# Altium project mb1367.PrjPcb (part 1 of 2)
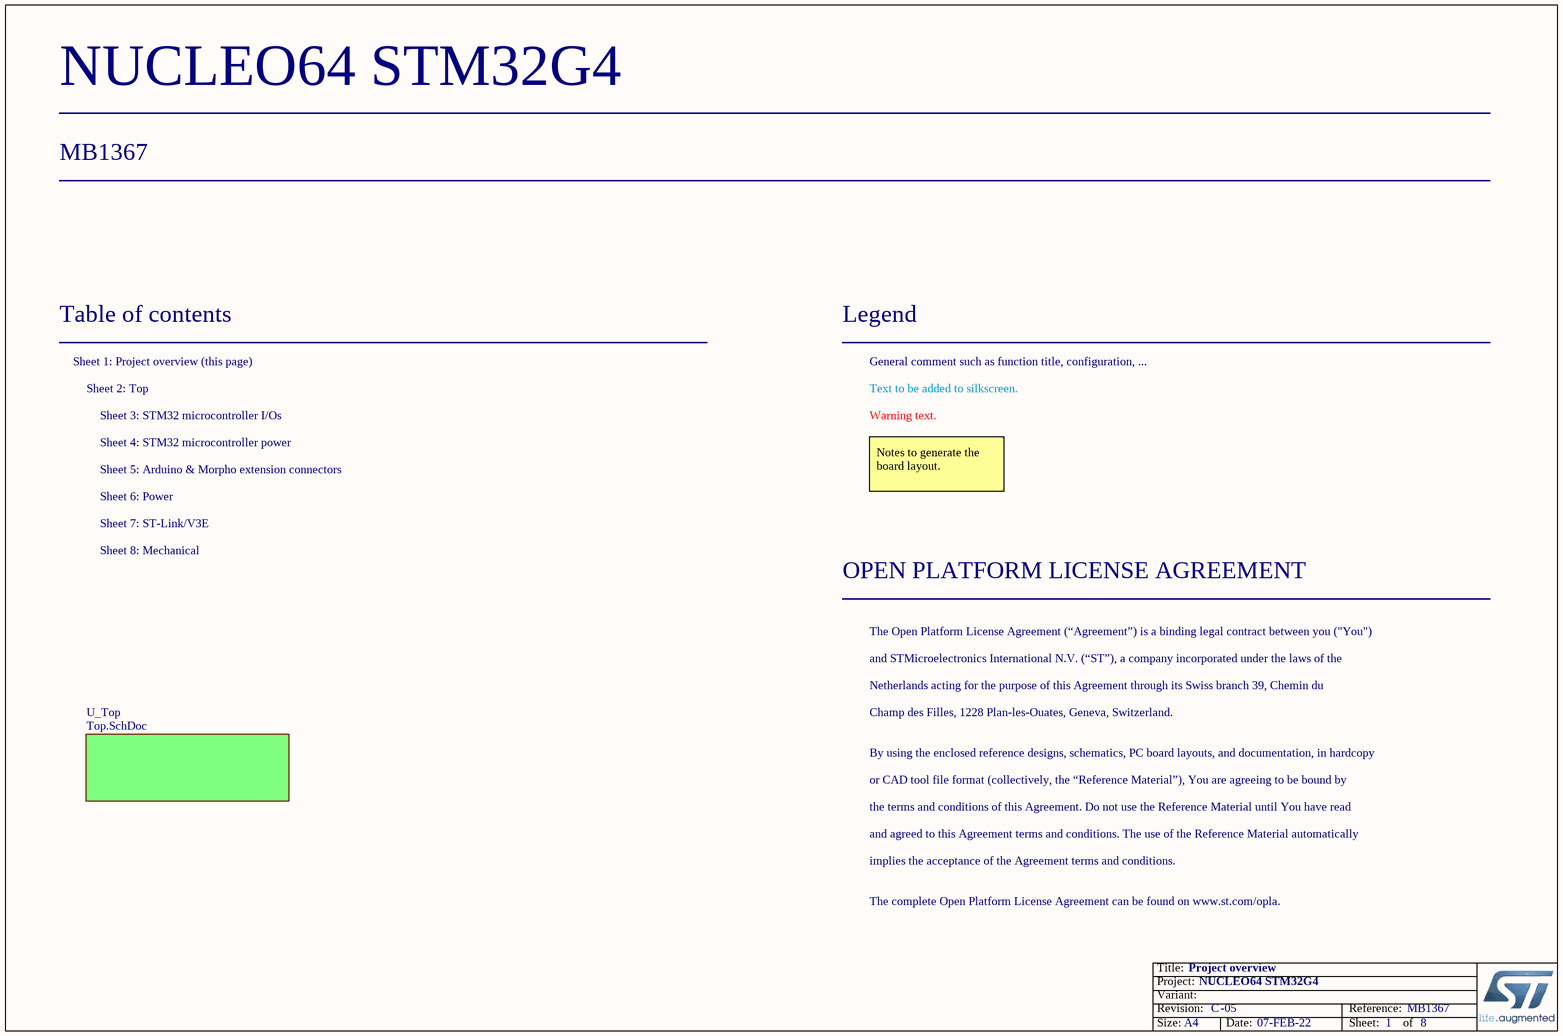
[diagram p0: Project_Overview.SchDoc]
Board_Assembly_Revision: 05; Board_Document_Date: 07-FEB-22; Board_Name: NUCLEO64 STM32G4; Board_PCB_Revision: C; Board_Reference: MB1367
8 sheets, 202 parts. Net scope: flat (ports and power ports of the same name join across sheets).
Board file: MB1367.PcbDoc
Sheets:
  Project_Overview.SchDoc
    U_Top = Top.SchDoc
      U_Arduino_extension_connectors = Arduino_extension_connectors.SchDoc
      U_Power = Power.SchDoc
      U_STM32_microcontroller_IOs = STM32_microcontroller_IOs.SchDoc
      U_STM32_microcontroller_power = STM32_microcontroller_power.SchDoc
      U_ST_LINK_V3E = ST_LINK_V3E.SchDoc
      Mechanical = Mechanical.SchDoc

## Sheet Project_Overview.SchDoc: Project overview
size A4; Date: Not used; ApprovedBy: Not used; CheckedBy: Not used; Author: Not used; CompanyName: STMicroelectronics; DrawnBy: Not used; Engineer: Not used; Organization: Not used; Address1: Not used; Address2: Not used; Address3: Not used; Address4: Not used; DocumentNumber: 1; Revision: Not used; SheetNumber: 1; SheetTotal: 8

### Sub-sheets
U_Top = Top.SchDoc: no entries

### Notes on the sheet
- Table of contents
- Sheet 1: Project overview (this page)
- Legend
- General comment such as function title, configuration, ...
- Sheet 2: Top
- Sheet 4: STM32 microcontroller power
- Sheet 3: STM32 microcontroller I/Os
- Text to be added to silkscreen.
- Warning text.
- Sheet 6: Power
- Sheet 5: Arduino & Morpho extension connectors
- Notes to generate the board layout.
- Sheet 7: ST-Link/V3E
- Sheet 8: Mechanical
- OPEN PLATFORM LICENSE AGREEMENT
- The Open Platform License Agreement (“Agreement”) is a binding legal contract between you ("You")
- and STMicroelectronics International N.V. (“ST”), a company incorporated under the laws of the
- Netherlands acting for the purpose of this Agreement through its Swiss branch 39, Chemin du
- Champ des Filles, 1228 Plan-les-Ouates, Geneva, Switzerland.
- By using the enclosed reference designs, schematics, PC board layouts, and documentation, in hardcopy
- or CAD tool file format (collectively, the “Reference Material”), You are agreeing to be bound by
- the terms and conditions of this Agreement. Do not use the Reference Material until You have read
- and agreed to this Agreement terms and conditions. The use of the Reference Material automatically
- implies the acceptance of the Agreement terms and conditions.
- The complete Open Platform License Agreement can be found on www.st.com/opla.

## Sheet Top.SchDoc: Top hierarchical view
size A4; Date: Not used; ApprovedBy: Not used; CheckedBy: Not used; Author: Not used; CompanyName: STMicroelectronics; DrawnBy: Not used; Engineer: Not used; Organization: Not used; Address1: Not used; Address2: Not used; Address3: Not used; Address4: Not used; DocumentNumber: 2; Revision: A-01-P3; SheetNumber: 2; SheetTotal: 8
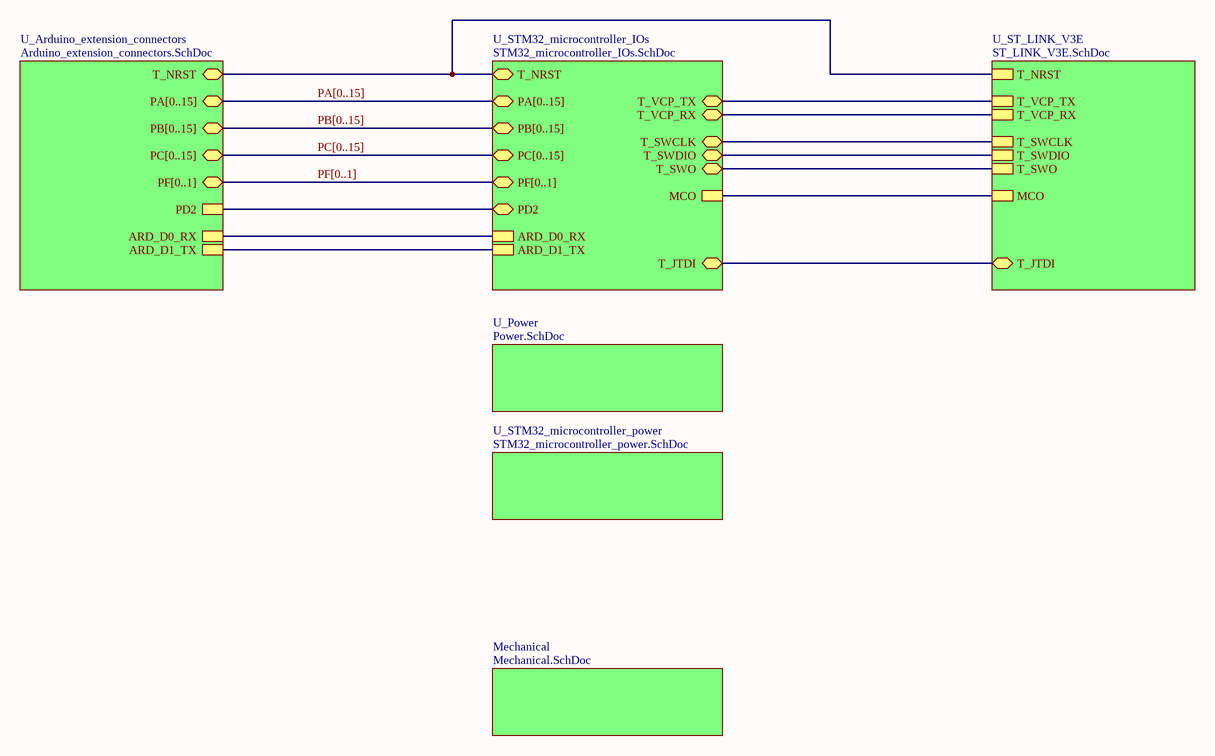
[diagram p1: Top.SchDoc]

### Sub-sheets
Mechanical = Mechanical.SchDoc: no entries
U_Arduino_extension_connectors = Arduino_extension_connectors.SchDoc: PA[0..15] (bidir), PB[0..15] (bidir), PC[0..15] (bidir), PD2, PF[0..1] (bidir), ARD_D0_RX, ARD_D1_TX, T_NRST
U_Power = Power.SchDoc: no entries
U_ST_LINK_V3E = ST_LINK_V3E.SchDoc: T_SWCLK, T_SWO, T_NRST, MCO, T_SWDIO, T_VCP_TX, T_VCP_RX, T_JTDI
U_STM32_microcontroller_IOs = STM32_microcontroller_IOs.SchDoc: PA[0..15] (bidir), PB[0..15] (bidir), PC[0..15] (bidir), PF[0..1] (bidir), ARD_D0_RX, ARD_D1_TX, MCO, PD2, T_NRST, T_VCP_TX, T_VCP_RX, T_SWCLK, T_SWO, T_SWDIO, T_JTDI
U_STM32_microcontroller_power = STM32_microcontroller_power.SchDoc: no entries

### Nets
(unnamed): sheet U_Arduino_extension_connectors/PD2, sheet U_STM32_microcontroller_IOs/PD2
(unnamed): sheet U_Arduino_extension_connectors/ARD_D0_RX, sheet U_STM32_microcontroller_IOs/ARD_D0_RX  [a separate net that carries the same name]
(unnamed): sheet U_Arduino_extension_connectors/ARD_D1_TX, sheet U_STM32_microcontroller_IOs/ARD_D1_TX  [a separate net that carries the same name]
(unnamed): sheet U_Arduino_extension_connectors/T_NRST, sheet U_STM32_microcontroller_IOs/T_NRST, sheet U_ST_LINK_V3E/T_NRST  [a separate net that carries the same name]
(unnamed): sheet U_STM32_microcontroller_IOs/MCO, sheet U_ST_LINK_V3E/MCO  [a separate net that carries the same name]
(unnamed): sheet U_STM32_microcontroller_IOs/T_VCP_TX, sheet U_ST_LINK_V3E/T_VCP_TX  [a separate net that carries the same name]
(unnamed): sheet U_STM32_microcontroller_IOs/T_VCP_RX, sheet U_ST_LINK_V3E/T_VCP_RX  [a separate net that carries the same name]
(unnamed): sheet U_STM32_microcontroller_IOs/T_SWCLK, sheet U_ST_LINK_V3E/T_SWCLK  [a separate net that carries the same name]
(unnamed): sheet U_STM32_microcontroller_IOs/T_SWO, sheet U_ST_LINK_V3E/T_SWO  [a separate net that carries the same name]
(unnamed): sheet U_STM32_microcontroller_IOs/T_SWDIO, sheet U_ST_LINK_V3E/T_SWDIO  [a separate net that carries the same name]
(unnamed): sheet U_STM32_microcontroller_IOs/T_JTDI, sheet U_ST_LINK_V3E/T_JTDI  [a separate net that carries the same name]

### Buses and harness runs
bus PA[0..15] = sheet U_Arduino_extension_connectors/PA[0..15] = sheet U_STM32_microcontroller_IOs/PA[0..15]
bus PB[0..15] = sheet U_Arduino_extension_connectors/PB[0..15] = sheet U_STM32_microcontroller_IOs/PB[0..15]
bus PC[0..15] = sheet U_Arduino_extension_connectors/PC[0..15] = sheet U_STM32_microcontroller_IOs/PC[0..15]
bus PF[0..1] = sheet U_Arduino_extension_connectors/PF[0..1] = sheet U_STM32_microcontroller_IOs/PF[0..1]

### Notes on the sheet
- Cuttable part on PCB

## Sheet Arduino_extension_connectors.SchDoc: Arduino & Morpho extension connectors
size A4; Date: Not used; ApprovedBy: Not used; CheckedBy: Not used; Author: Not used; CompanyName: STMicroelectronics; DrawnBy: Not used; Engineer: Not used; Organization: Not used; Address1: Not used; Address2: Not used; Address3: Not used; Address4: Not used; DocumentNumber: 5; Revision: Not used; SheetNumber: 5; SheetTotal: 8
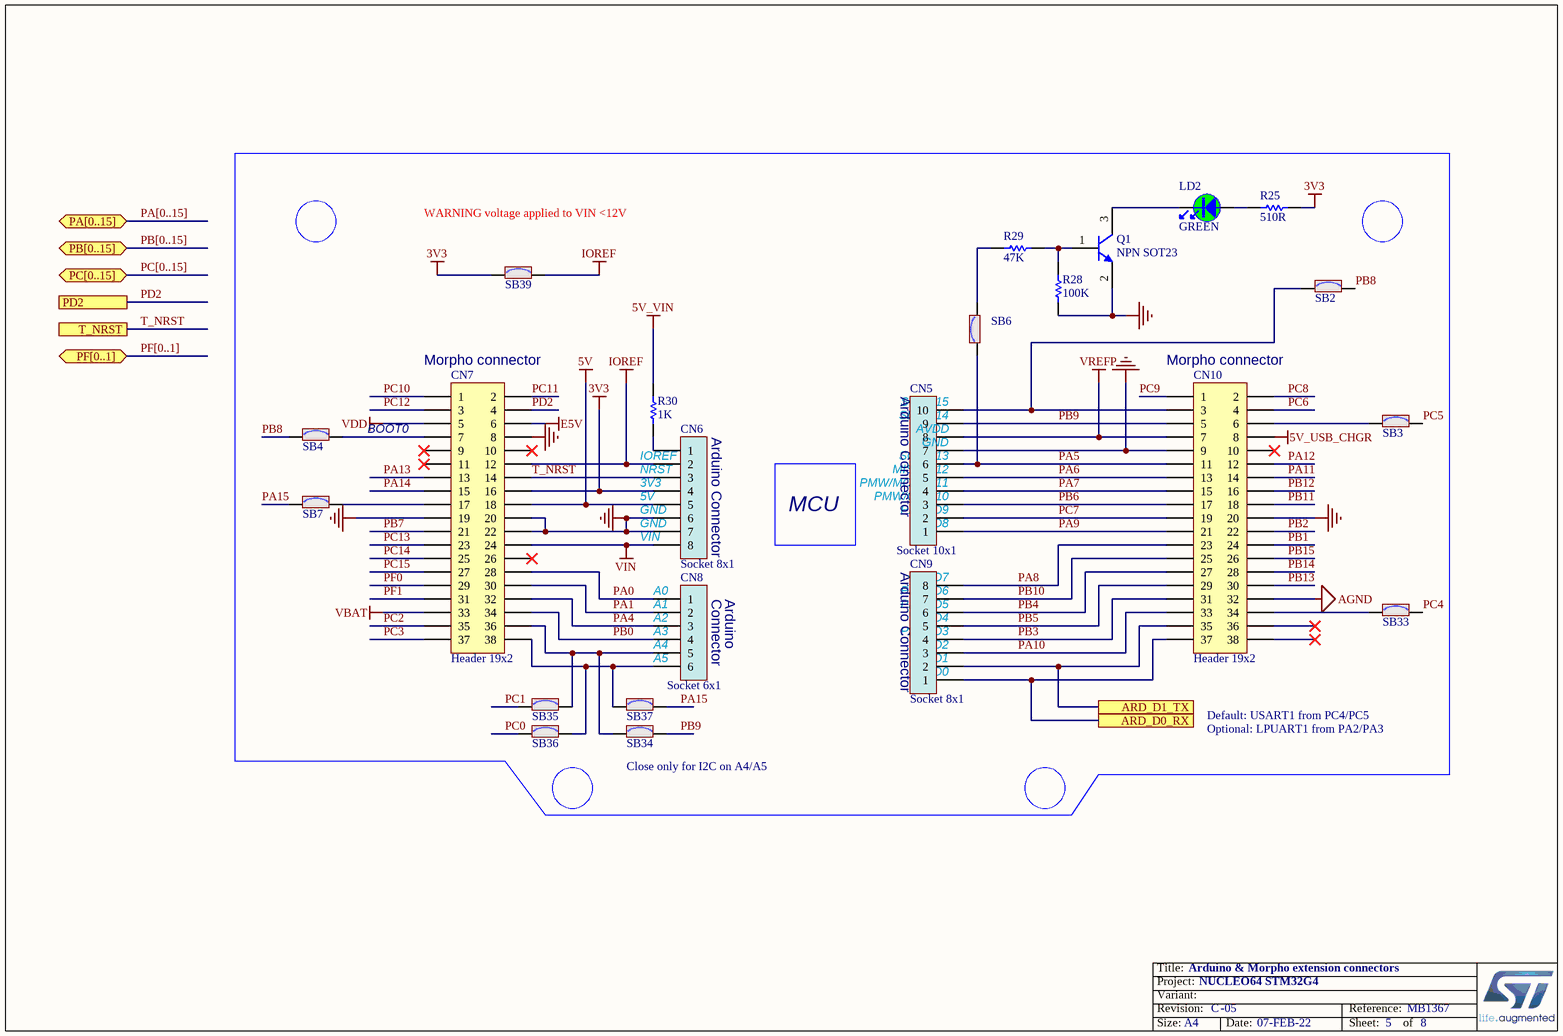
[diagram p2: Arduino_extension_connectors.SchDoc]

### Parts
CN5  value Socket 10x1  [CON_SAMTEC_SSW-110-03-X-S]
CN6  value Socket 8x1  [CON_SAMTEC_SSW-108-03-X-S]
CN7  value Header 19x2  [CON_SAMTEC_TSW-119-09-X-D]
CN8  value Socket 6x1  [CON_SAMTEC_SSW-106-03-X-S]
CN9  value Socket 8x1  [CON_SAMTEC_SSW-108-03-X-S]
CN10  value Header 19x2  [CON_SAMTEC_TSW-119-09-X-D]
LD2  value GREEN  [LED_0603_GREEN]  (hidden comment: LED_green)
Q1  value NPN SOT23  [NPN_SOT23]
R25  value 510R  [R0603]
R28  value 100K  [R0603]
R29  value 47K  [R0603]
R30  value 1K  [R0603]
SB2  (no value)  [SOLDER-BRIDGE_R0603-0R]
SB3  (no value)  [SOLDER-BRIDGE_R0603-0R]
SB4  (no value)  [SOLDER-BRIDGE_R0603-0R]
SB6  (no value)  [SOLDER-BRIDGE_R0603-0R]
SB7  (no value)  [SOLDER-BRIDGE_R0603-0R]
SB33  (no value)  [SOLDER-BRIDGE_R0603-0R]
SB34  (no value)  [SOLDER-BRIDGE_R0603-0R]
SB35  (no value)  [SOLDER-BRIDGE_R0603-0R]
SB36  (no value)  [SOLDER-BRIDGE_R0603-0R]
SB37  (no value)  [SOLDER-BRIDGE_R0603-0R]
SB39  (no value)  [SOLDER-BRIDGE_R0603-0R]

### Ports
ARD_D0_RX, ARD_D1_TX, PA[0..15] (bidir), PB[0..15] (bidir), PC[0..15] (bidir), PD2, PF[0..1] (bidir), T_NRST

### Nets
3V3: CN6.4 CN7.16 R25.1 SB39.1
5V: CN6.5 CN7.18
5V_USB_CHGR: CN10.8
5V_VIN: R30.2
AGND: CN10.32
E5V: CN7.6
GND: CN5.7 CN6.6 CN6.7 CN7.8 CN7.19 CN7.20 CN7.22 CN10.9 CN10.20 Q1.2(E) R28.1
IOREF: CN6.2 CN7.12 SB39.2
VBAT: CN7.33
VDD: CN7.5
VIN: CN6.8 CN7.24
VREFP: CN5.8 CN10.7
ARD_D0_RX: CN9.1 CN10.37 ; port ARD_D0_RX
ARD_D1_TX: CN9.2 CN10.35 ; port ARD_D1_TX
PA0: CN7.28 CN8.1
PA1: CN7.30 CN8.2
PA4: CN7.32 CN8.3
PA5: CN5.6 CN10.11 SB6.1
PA6: CN5.5 CN10.13
PA7: CN5.4 CN10.15
PA8: CN9.8 CN10.23
PA9: CN5.1 CN10.21
PA10: CN9.3 CN10.33
PA11: CN10.14
PA12: CN10.12
PA13: CN7.13
PA14: CN7.15
PA15: SB7.1 SB37.2
PB0: CN7.34 CN8.4
PB1: CN10.24
PB2: CN10.22
PB3: CN9.4 CN10.31
PB4: CN9.6 CN10.27
PB5: CN9.5 CN10.29
PB6: CN5.3 CN10.17
PB7: CN7.21
PB8: SB2.2 SB4.1
PB9: CN5.9 CN10.5 SB34.2
PB10: CN9.7 CN10.25
PB11: CN10.18
PB12: CN10.16
PB13: CN10.30
PB14: CN10.28
PB15: CN10.26
PC0: SB36.1
PC1: SB35.1
PC2: CN7.35
PC3: CN7.37
PC4: SB33.2
PC5: SB3.2
PC6: CN10.4
PC7: CN5.2 CN10.19
PC8: CN10.2
PC9: CN10.1
PC10: CN7.1
PC11: CN7.2
PC12: CN7.3
PC13: CN7.23
PC14: CN7.25
PC15: CN7.27
PD2: CN7.4 ; port PD2
PF0: CN7.29
PF1: CN7.31
T_NRST: CN6.3 CN7.14 ; port T_NRST
NetCN5_10: CN5.10 CN10.3 SB2.1
NetCN6_1: CN6.1 R30.1
NetCN7_7: CN7.7 SB4.2
NetCN7_17: CN7.17 SB7.2
NetCN7_36: CN7.36 CN8.5 SB34.1 SB35.2
NetCN7_38: CN7.38 CN8.6 SB36.2 SB37.1
NetCN10_6: CN10.6 SB3.1
NetCN10_34: CN10.34 SB33.1
NetLD2_1: LD2.1 R25.2
NetLD2_2: LD2.2 Q1.3(C)
NetQ1_1: Q1.1(B) R28.2 R29.2
NetR29_1: R29.1 SB6.2

Not connected (* = marked no-connect by the designer): CN7 9* 10* 11* 26*; CN10 10* 36* 38*

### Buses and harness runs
bus PA[0..15] = port PA[0..15]
bus PB[0..15] = port PB[0..15]
bus PC[0..15] = port PC[0..15]
bus PF[0..1] = port PF[0..1]

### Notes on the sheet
- WARNING voltage applied to VIN <12V
- (near CN7) Morpho connector
- (near CN10) Morpho connector
- (near CN7) BOOT0
- (near CN6) Arduino Connector
- (near CN5) Arduino Connector
- (near CN5) SDA/D14
- (near CN5) SCL/D15
- (near CN5) AVDD
- (near CN5) GND
- (near CN6) GND
- (near CN6) 5V
- (near CN6) 3V3
- (near CN6) NRST
- (near CN6) IOREF
- MCU
- (near CN5) PMW/D9
- (near CN5) PMW/CS/D10
- (near CN5) SCK/D13
- (near CN5) MISO/D12
- (near CN5) PMW/MOSI/D11
- (near CN6) VIN
- (near CN9) Arduino Connector
- (near CN9) D7
- (near CN5) D8
- (near CN8) A0
- (near CN8) A1
- (near CN8) A2
- (near CN8) A3
- (near CN8) A4
- (near CN8) Connector
- (near CN8) Arduino
- (near CN9) D2
- (near CN9) D4
- (near CN9) PMW/D3
- (near CN9) PMW/D5
- (near CN9) PMW/D6
- (near CN8) A5
- (near CN9) RX/D0
- (near CN9) TX/D1
- (near SB34) Close only for I2C on A4/A5
- Default: USART1 from PC4/PC5
  Optional: LPUART1 from PA2/PA3

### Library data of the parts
CN5 = MCD-00262: Socket, 10x1, 2.54mm, VR, TH, Height 8.51mm/10mm; Manufacturer_Part_Number: SSW-110-03-x-S; Manufacturer: SAMTEC; Part_Type: Connector; Provided_By: SUBCO
CN6 CN9 = MCD-00261: Socket, 8x1, 2.54mm, VR, TH, Height 8.51mm/10mm; Manufacturer_Part_Number: SSW-108-03-x-S; Manufacturer: SAMTEC; Part_Type: Connector; Provided_By: SUBCO
CN7 CN10 = MCD-00213: Header, 19x2, 2,54mm, VR, TH, Height 5.84mm/10.16mm; Manufacturer_Part_Number: TSW-119-09-x-D; Manufacturer: SAMTEC; Part_Type: Connector; Provided_By: SUBCO
CN8 = MCD-00260: Socket, 6x1, 2.54mm, VR, TH, Height 8.51mm/10mm; Manufacturer_Part_Number: SSW-106-03-x-S; Manufacturer: SAMTEC; Part_Type: Connector; Provided_By: SUBCO
LD2 = MCD-02520: LED, GREEN, 0603, VF : 2.4V max ; IF: 20mA; Part_Type: Display; Part_Preference: Recommended; Manufacturer: OSRAM OPTO SEMICONDUCTORS; Manufacturer_Part_Number: LG Q396-PS-35; ShowFields: YES; ID: 4626
Q1 = MCD-00073: NPN Bipolar Transistor; Part_Type: IC; Manufacturer_Part_Number: BSR14; Manufacturer: ON SEMICONDUCTOR; Alternate_Manufacturer_Part_Number: MMBT2222LT1G / MMBT2222ALT1G / MMBT2222ALT3G; ECCN_US: EAR99; ECCN_EU: NEC; Provided_By: SUBCO
R25 = MCD-00225: Resistor,510R,0603,1%,1/10W; Manufacturer_Part_Number: RC0603FR-07510RL; Manufacturer: YAGEO; ECCN_US: EAR99; ECCN_EU: NEC; Provided_By: SUBCO
R28 = MCD-00223: Resistor,100K,0603,1%,1/10W; Manufacturer_Part_Number: RC0603FR-07100KL; Manufacturer: YAGEO; Provided_By: Subcon; Initial_Board_Reference: MB1319
R29 = MCD-00222: Resistor,47K,0603,1%,1/10W; Manufacturer_Part_Number: RC0603FR-0747KL; Manufacturer: YAGEO; ECCN_US: EAR99; ECCN_EU: NEC; Provided_By: SUBCO
R30 = MCD-00070: Resistor,1K,0603,1%,1/10W; Manufacturer_Part_Number: RC0603FR-071KL; Manufacturer: YAGEO; Provided_By: Subcon; Initial_Board_Reference: MB1274
SB2-SB4 SB6 SB7 SB33-SB37 SB39 = MCD-00071: Solder Bridge ON; Part_Type: Mechanical; Manufacturer_Part_Number: RC0603JR-070RL; Manufacturer: YAGEO; Provided_By: SUBCO

## Sheet Power.SchDoc: Main power 5V / 3V3
size A4; Date: Not used; ApprovedBy: Not used; CheckedBy: Not used; Author: Not used; CompanyName: STMicroelectronics; DrawnBy: Not used; Engineer: Not used; Organization: Not used; Address1: Not used; Address2: Not used; Address3: Not used; Address4: Not used; DocumentNumber: 6; Revision: Not used; SheetNumber: 6; SheetTotal: 8
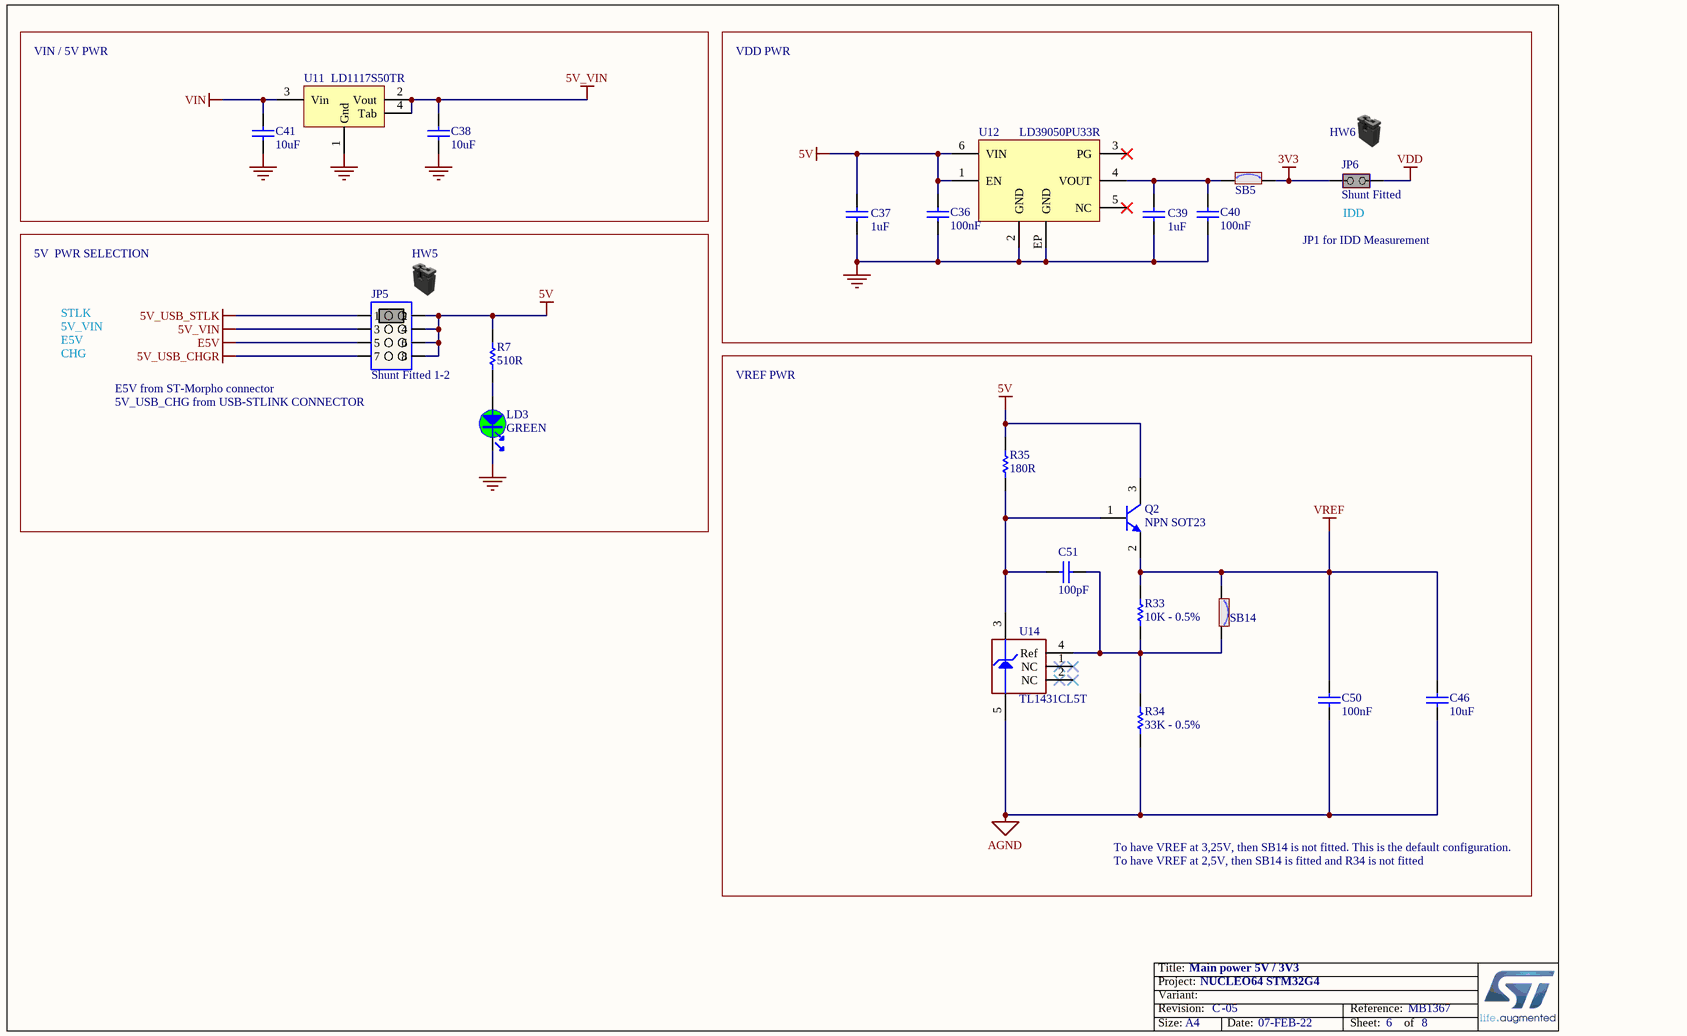
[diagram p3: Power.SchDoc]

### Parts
C36  value 100nF  [C0402]
C37  value 1uF  [C0603]
C38  value 10uF  [C0805]
C39  value 1uF  [C0603]
C40  value 100nF  [C0402]
C41  value 10uF  [C0805]
C46  value 10uF  [C0603]
C50  value 100nF  [C0603]
C51  value 100pF  [C0603]
HW5  (no value)  (mechanical)
HW6  (no value)  (mechanical)
JP5  value Shunt Fitted 1-2  [CON_SAMTEC_TSW-104-07-X-D]
JP6  Shunt Fitted  [CON_SAMTEC_TSW-102-07-G-S]
LD3  value GREEN  [LED_0603_GREEN]  (hidden comment: LED_green)
Q2  value NPN SOT23  [NPN_SOT23]
R7  value 510R  [R0603]
R33  value 10K - 0.5%  [R0603]
R34  value 33K - 0.5%  [R0603]
R35  value 180R  [R0603]
SB5  (no value)  [SOLDER-BRIDGE_R0603-0R]
SB14  (no value)  [SOLDER-BRIDGE_R0603-0R]
U11  value LD1117S50TR  [REG_SOT223-TAB]
U12  value LD39050PU33R  [ICC_DFN6-EPAD_3X3_P095]
U14  value TL1431CL5T  [ICC_SOT23-5L_H1P45]

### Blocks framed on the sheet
VIN / 5V PWR: C38 C41 U11
VREF PWR: C46 C50 C51 Q2 R33-R35 SB14 U14

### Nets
3V3: JP6.1(COMMON) SB5.2
5V: C36.2 C37.2 JP5.2 JP5.4 JP5.6 JP5.8 Q2.3(C) R7.2 R35.2 U12.1(EN) U12.6(VIN)
5V_USB_CHGR: JP5.7
5V_USB_STLK: JP5.1
5V_VIN: C38.2 JP5.3 U11.2(Vout) U11.4(Tab)
AGND: C46.1 C50.1 R34.1 U14.5(Anode)
E5V: JP5.5
GND: C36.1 C37.1 C38.1 C39.1 C40.1 C41.1 LD3.2 U11.1(Gnd) U12.2(GND) U12.EP(GND)
VDD: JP6.2(NO)
VIN: C41.2 U11.3(Vin)
VREF: C46.2 C50.2 Q2.2(E) R33.2 SB14.1
NetC39_2: C39.2 C40.2 SB5.1 U12.4(VOUT)
NetC51_1: C51.1 Q2.1(B) R35.1 U14.3(Cathode)
NetC51_2: C51.2 R33.1 R34.2 SB14.2 U14.4(Ref)
NetLD3_1: LD3.1 R7.1

Not connected (* = marked no-connect by the designer): U12 3(PG)* 5(NC)*; U14 1(NC)* 2(NC)*

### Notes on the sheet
- VDD PWR
- JP1 for IDD Measurement
- (near JP6) IDD
- 5V  PWR SELECTION
- STLK
- E5V
- 5V_VIN
- CHG
- E5V from ST-Morpho connector
- 5V_USB_CHG from USB-STLINK CONNECTOR
- To have VREF at 3,25V, then SB14 is not fitted. This is the default configuration.
- To have VREF at 2,5V, then SB14 is fitted and R34 is not fitted

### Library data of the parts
C36 C40 = MCD-00102: Capacitor, MLCC, 100nF, 16V, X7R, 10%, 0402, T=0,5mm; Manufacturer_Part_Number: CC0402KRX7R7BB104; Manufacturer: YAGEO; Provided_By: Subcon; Initial_Board_Reference: MB1262
C37 C39 = MCD-00010: Capacitor, MLCC, 1uF, 16V, X5R, 10%, 0603, T=0,8mm; Manufacturer_Part_Number: CC0603KRX5R7BB105; Manufacturer: YAGEO; Provided_By: Subcon; Initial_Board_Reference: MB1274
C38 C41 = MCD-00014: Capacitor, MLCC, 10uF, 25V, X5R, 10%, 0805, T=0,85mm; Manufacturer_Part_Number: CC0805KRX5R8BB106; Manufacturer: YAGEO; ECCN_US: EAR99; ECCN_EU: NEC; Provided_By: SUBCO
C46 = MCD-01124: Capacitor, MLCC, 10uF, 10V, X5R, 10%, 0603, T=0.8mm; Manufacturer_Part_Number: GRM188R61A106KAAL; Manufacturer: MURATA; ECCN_US: EAR99; ECCN_EU: NEC; Provided_By: SUBCO
C50 = MCD-00211: Capacitor, MLCC, 100nF, 16V, X7R, 10%, 0603, T=0,8mm; Manufacturer_Part_Number: CC0603KRX7R7BB104; Manufacturer: YAGEO; ECCN_US: EAR99; ECCN_EU: NEC; Provided_By: SUBCO
C51 = MCD-01101: Capacitor,100pF,50V,X7R,10%,0603; Manufacturer_Part_Number: 06035C101JAT4A; Manufacturer: AVX; ECCN_US: EAR99; ECCN_EU: NEC; Provided_By: SUBCO
HW5 HW6 = MCD-00043: SHUNT 2.54mm BLACK; Manufacturer_Part_Number: SNT-100-BK-G; Manufacturer: SAMTEC; Part_Type: Mechanical; Provided_By: Subcon; Initial_Board_Reference: MB1274
JP5 = MCD-00686: Header, 4x2, 2,54mm, VR, TH, Height 5.84mm/2.54mm - Shunt Fitted 1-2; Part_Type: Connector; Manufacturer_Part_Number: TSW-104-07-x-D; Manufacturer: SAMTEC; Provided_By: SUBCO
JP6 = MCD-00683: Header, 2x1, 2,54mm, VR, TH, Height 5.84mm/2.54mm - Shunt Fitted by default; Part_Type: Connector; Manufacturer_Part_Number: TSW-102-07-x-S; Manufacturer: SAMTEC; Provided_By: Subcon; Initial_Board_Reference: MB1331
LD3 = MCD-02520: as LD2 on sheet Arduino_extension_connectors
Q2 = MCD-00073: as Q1 on sheet Arduino_extension_connectors
R7 = MCD-00225: as R25 on sheet Arduino_extension_connectors
R33 = MCD-01215: resistor, 10K, 0603, 0.5%, 1/10W; Manufacturer_Part_Number: RC0603DR-0710KL; Manufacturer: YAGEO; ECCN_US: EAR99; ECCN_EU: NEC; Provided_By: SUBCO
R34 = MCD-01209: Resistor,33K,0603,0.5%,1/10W; Manufacturer_Part_Number: RC0603DR-0733KL; Manufacturer: YAGEO; ECCN_US: EAR99; ECCN_EU: NEC; Provided_By: SUBCO
R35 = MCD-00342: Resistor,180R,0603,1%,1/10W; Manufacturer_Part_Number: RC0603FR-07180RL; Manufacturer: YAGEO; ECCN_US: EAR99; ECCN_EU: NEC; Provided_By: SUBCO
SB5 SB14 = MCD-00071: as SB2 on sheet Arduino_extension_connectors
U11 = MCD-00088: IC REG LDO 5V 0.8A SOT223; Manufacturer: STMICROELECTRONICS; BMS_Part_Number: 9176133; ECCN_US: EAR99; ECCN_EU: NEC; Provided_By: SUBCO with ST control
U12 = MCD-00215: Low quiescent current and low noise voltage regulators; Manufacturer: STMICROELECTRONICS; Part_Type: IC; BMS_Part_Number: 9176126; ECCN_US: EAR99; ECCN_EU: NEC; Provided_By: SUBCO with ST control
U14 = MCD-01802: Programmable voltage reference with 0.4% voltage precision; Part_Type: IC; Manufacturer: STMICROELECTRONICS; BMS_Part_Number: 9176334; ECCN_US: EAR99; ECCN_EU: NEC; Provided_By: SUBCO with ST control

## Sheet STM32_microcontroller_IOs.SchDoc: STM32 microcontroller I/Os
size A4; Date: Not used; ApprovedBy: Not used; CheckedBy: Not used; Author: Not used; CompanyName: STMicroelectronics; DrawnBy: Not used; Engineer: Not used; Organization: Not used; Address1: Not used; Address2: Not used; Address3: Not used; Address4: Not used; DocumentNumber: 3; Revision: Not used; SheetNumber: 3; SheetTotal: 8
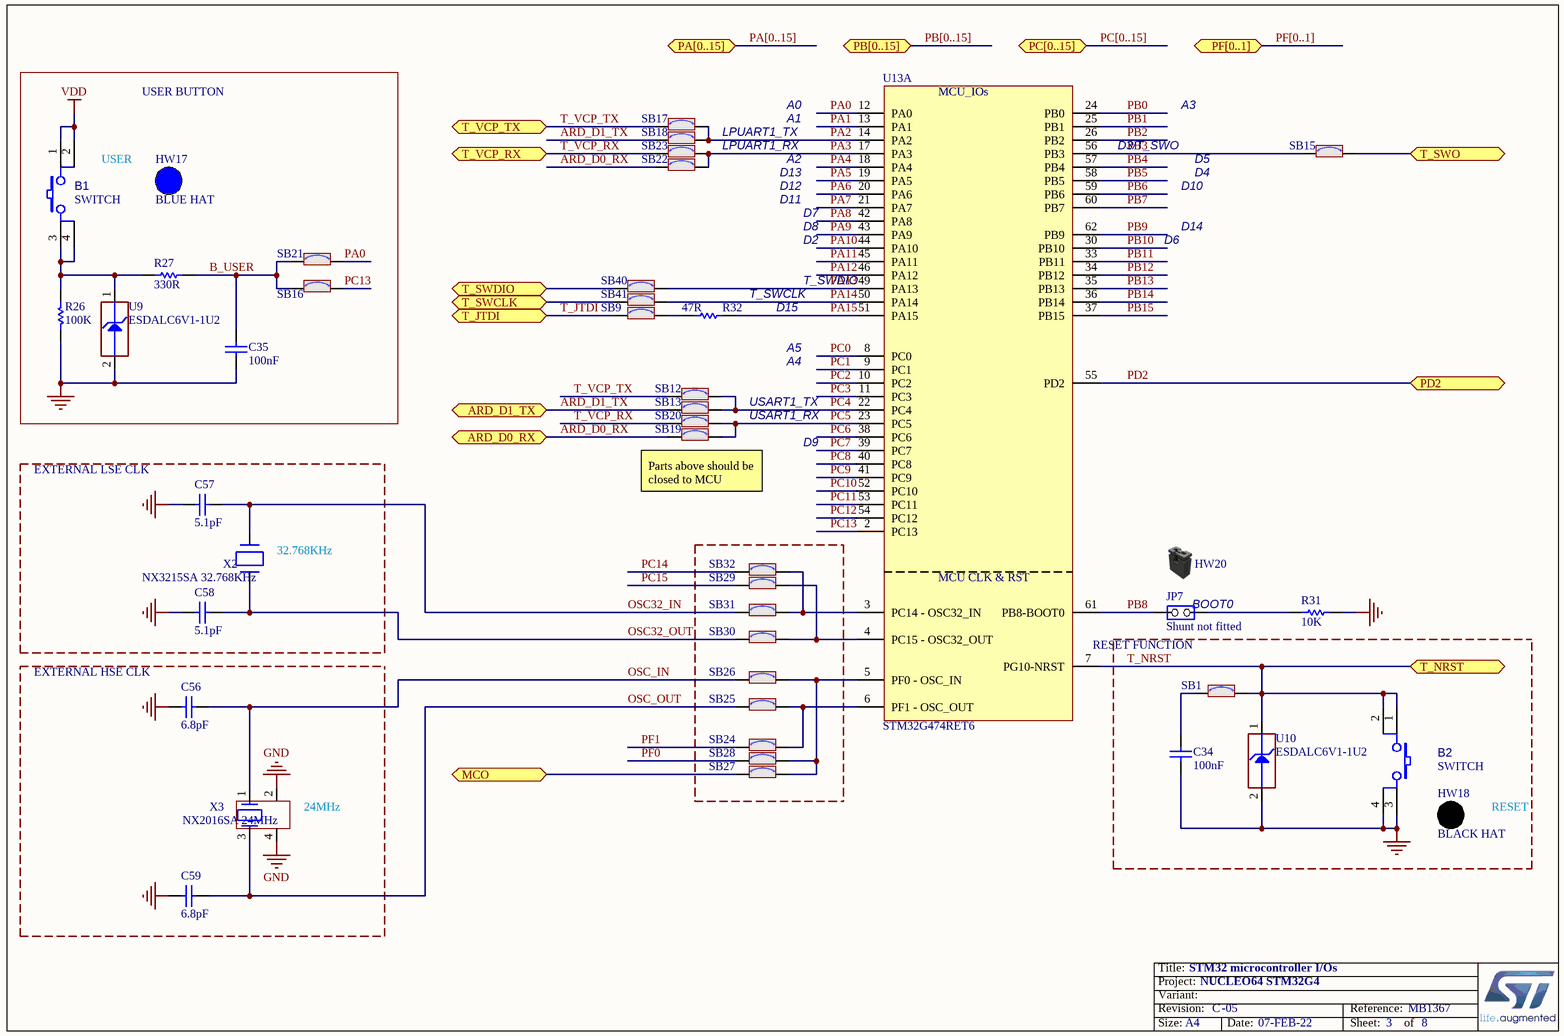
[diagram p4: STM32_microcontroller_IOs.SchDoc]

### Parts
B1  value SWITCH  [SWI_WEALTHMETAL_TD-0341_4P_BLUE]
B2  value SWITCH  [SWI_WEALTHMETAL_TD-0341_4P_BLACK]
C34  value 100nF  [C0402]
C35  value 100nF  [C0402]
C56  value 6.8pF  [C0402]
C57  value 5.1pF  [C0402]
C58  value 5.1pF  [C0402]
C59  value 6.8pF  [C0402]
HW17  value BLUE HAT  (mechanical)
HW18  value BLACK HAT  (mechanical)
HW20  (no value)  (mechanical)
JP7  value Shunt not fitted  [CON_SAMTEC_TSW-102-07-G-S]
R26  value 100K  [R0603]
R27  value 330R  [R0603]
R31  value 10K  [R0603]
R32  value 47R  [R0402]
SB1  (no value)  [SOLDER-BRIDGE_R0603-0R]
SB9  (no value)  [SOLDER-BRIDGE_R0603-0R]
SB12  (no value)  [SOLDER-BRIDGE_R0603-0R]
SB13  (no value)  [SOLDER-BRIDGE_R0603-0R]
SB15  (no value)  [SOLDER-BRIDGE_R0603-0R]
SB16  (no value)  [SOLDER-BRIDGE_R0603-0R]
SB17  (no value)  [SOLDER-BRIDGE_R0603-0R]
SB18  (no value)  [SOLDER-BRIDGE_R0603-0R]
SB19  (no value)  [SOLDER-BRIDGE_R0603-0R]
SB20  (no value)  [SOLDER-BRIDGE_R0603-0R]
SB21  (no value)  [SOLDER-BRIDGE_R0603-0R]
SB22  (no value)  [SOLDER-BRIDGE_R0603-0R]
SB23  (no value)  [SOLDER-BRIDGE_R0603-0R]
SB24  (no value)  [SOLDER-BRIDGE_R0603-0R]
SB25  (no value)  [SOLDER-BRIDGE_R0603-0R]
SB26  (no value)  [SOLDER-BRIDGE_R0603-0R]
SB27  (no value)  [SOLDER-BRIDGE_R0603-0R]
SB28  (no value)  [SOLDER-BRIDGE_R0603-0R]
SB29  (no value)  [SOLDER-BRIDGE_R0603-0R]
SB30  (no value)  [SOLDER-BRIDGE_R0603-0R]
SB31  (no value)  [SOLDER-BRIDGE_R0603-0R]
SB32  (no value)  [SOLDER-BRIDGE_R0603-0R]
SB40  (no value)  [SOLDER-BRIDGE_R0603-0R]
SB41  (no value)  [SOLDER-BRIDGE_R0603-0R]
U9  value ESDALC6V1-1U2  [ESD_ST0201]
U10  value ESDALC6V1-1U2  [ESD_ST0201]
U13  value STM32G474RET6  [ICC_LQFP64_10X10_P050_SOCKET_YAMAICHI_IC149-064-069-B5_NM]  (part A of 2)
X2  value NX3215SA 32.768KHz  [CRY_NX3215SA_2P]
X3  value NX2016SA 24MHz  [CRY_NX2016SA_4P]

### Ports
ARD_D0_RX, ARD_D1_TX, MCO, PA[0..15] (bidir), PB[0..15] (bidir), PC[0..15] (bidir), PD2, PF[0..1] (bidir), T_JTDI, T_NRST, T_SWCLK, T_SWDIO, T_SWO, T_VCP_RX, T_VCP_TX

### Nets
GND: B2.3 B2.4 C34.1 C35.1 C56.1 C57.2 C58.2 C59.1 R26.1 R31.1 U9.2(GND) U10.2(GND) X3.2 X3.4
VDD: B1.1 B1.2
ARD_D0_RX: SB19.2 SB22.2 ; port ARD_D0_RX
ARD_D1_TX: SB13.2 SB18.2 ; port ARD_D1_TX
B_USER: C35.2 R27.2 SB16.1 SB21.1
MCO: SB27.1 ; port MCO
OSC32_IN: C57.1 SB31.1 X2.2(X2)
OSC32_OUT: C58.1 SB30.1 X2.1(X1)
OSC_IN: C56.2 SB26.1 X3.1
OSC_OUT: C59.2 SB25.1 X3.3
PA0: SB21.2 U13.12(PA0)
PA1: U13.13(PA1)
PA2: SB17.2 SB18.1 U13.14(PA2)
PA3: SB22.1 SB23.2 U13.17(PA3)
PA4: U13.18(PA4)
PA5: U13.19(PA5)
PA6: U13.20(PA6)
PA7: U13.21(PA7)
PA8: U13.42(PA8)
PA9: U13.43(PA9)
PA10: U13.44(PA10)
PA11: U13.45(PA11)
PA12: U13.46(PA12)
PA13: SB40.2 U13.49(PA13)
PA14: SB41.2 U13.50(PA14)
PA15: R32.2 U13.51(PA15)
PB0: U13.24(PB0)
PB1: U13.25(PB1)
PB2: U13.26(PB2)
PB3: SB15.1 U13.56(PB3)
PB4: U13.57(PB4)
PB5: U13.58(PB5)
PB6: U13.59(PB6)
PB7: U13.60(PB7)
PB8: JP7.1(COMMON) U13.61(PB8-BOOT0)
PB9: U13.62(PB9)
PB10: U13.30(PB10)
PB11: U13.33(PB11)
PB12: U13.34(PB12)
PB13: U13.35(PB13)
PB14: U13.36(PB14)
PB15: U13.37(PB15)
PC0: U13.8(PC0)
PC1: U13.9(PC1)
PC2: U13.10(PC2)
PC3: U13.11(PC3)
PC4: SB12.2 SB13.1 U13.22(PC4)
PC5: SB19.1 SB20.2 U13.23(PC5)
PC6: U13.38(PC6)
PC7: U13.39(PC7)
PC8: U13.40(PC8)
PC9: U13.41(PC9)
PC10: U13.52(PC10)
PC11: U13.53(PC11)
PC12: U13.54(PC12)
PC13: SB16.2 U13.2(PC13)
PC14: SB32.1
PC15: SB29.1
PD2: U13.55(PD2) ; port PD2
PF0: SB28.1
PF1: SB24.1
T_JTDI: SB9.1 ; port T_JTDI
T_NRST: B2.1 B2.2 SB1.2 U10.1(IO1) U13.7(PG10-NRST) ; port T_NRST
T_SWCLK: SB41.1 ; port T_SWCLK
T_SWDIO: SB40.1 ; port T_SWDIO
T_SWO: SB15.2 ; port T_SWO
T_VCP_RX: SB20.1 SB23.1 ; port T_VCP_RX
T_VCP_TX: SB12.1 SB17.1 ; port T_VCP_TX
NetB1_3: B1.3 B1.4 R26.2 R27.1 U9.1(IO1)
NetC34_2: C34.2 SB1.1
NetJP7_2: JP7.2(NO) R31.2
NetR32_1: R32.1 SB9.2
NetSB24_2: SB24.2 SB25.2 U13.6(PF1_-_OSC_OUT)
NetSB26_2: SB26.2 SB27.2 SB28.2 U13.5(PF0_-_OSC_IN)
NetSB29_2: SB29.2 SB30.2 U13.4(PC15_-_OSC32_OUT)
NetSB31_2: SB31.2 SB32.2 U13.3(PC14_-_OSC32_IN)

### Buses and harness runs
bus PA[0..15] = port PA[0..15]
bus PB[0..15] = port PB[0..15]
bus PC[0..15] = port PC[0..15]
bus PF[0..1] = port PF[0..1]

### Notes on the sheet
- USER BUTTON
- A0
- A3
- USER
- LPUART1_TX
- LPUART1_RX
- A1
- A2
- D13
- D3/T_SWO
- D4
- D5
- D12
- D11
- D2
- D7
- D8
- D14
- D10
- D6
- (near R32) T_SWCLK
- D15
- (near R32) T_SWDIO
- A4
- A5
- USART1_RX
- USART1_TX
- D9
- EXTERNAL LSE CLK
- (near SB19) Parts above should be closed to MCU
- (near X2) 32.768KHz
- RESET FUNCTION
- BOOT0
- EXTERNAL HSE CLK
- (near X3) 24MHz
- RESET

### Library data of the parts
B1 = MCD-00002: Non-Open Push-Button 0.1A 24V; Manufacturer_Part_Number: TD-0341; Manufacturer: WEALTHMETAL; Part_Type: Misc; Provided_By: SUBCO
B2 = MCD-00001: Non-Open Push-Button 0.1A 24V BLACK; Manufacturer_Part_Number: TD-0341; Manufacturer: WEALTHMETAL; Part_Type: Misc; Provided_By: SUBCO
C34 C35 = MCD-00102: as C36 on sheet Power
C56 C59 = MCD-00674: Capacitor, MLCC, 6.8pF, 50V, NPO, +-0.25pF, 0402, T=0.5mm; Manufacturer_Part_Number: CC0402CRNPO9BN6R8; Manufacturer: YAGEO; Provided_By: SUBCO
C57 C58 = MCD-00003: Capacitor, MLCC, 5.1pF, 50V, NPO, +-0.25pF, 0402, T=0.5mm; Manufacturer_Part_Number: CC0402CRNPO9BN5R1; Manufacturer: YAGEO; ECCN_US: EAR99; ECCN_EU: NEC; Provided_By: SUBCO
HW17 = MCD-00634: Blue Hat for switch TD0341X-G01-BLU; Part_Type: Mechanical; Manufacturer_Part_Number: 988.16.09.3.00002_SH-517; Manufacturer: JIUBABA; Provided_By: SUBCO
HW18 = MCD-00635: Black Hat for switch TD0341X-G01-BLA; Part_Type: Mechanical; Manufacturer_Part_Number: 988.16.09.3.00003_SH-517; Manufacturer: JIUBABA; Provided_By: SUBCO
HW20 = MCD-00043: as HW5 on sheet Power
JP7 = MCD-00045: Header, 2x1, 2,54mm, VR, TH, Height 5.84mm/2.54mm; Part_Type: Connector; Manufacturer_Part_Number: TSW-102-07-x-S; Manufacturer: SAMTEC; Provided_By: Subcon; Initial_Board_Reference: MB1274
R26 = MCD-00223: as R28 on sheet Arduino_extension_connectors
R27 = MCD-00197: Resistor,330R,0603,1%,1/10W; Manufacturer_Part_Number: RC0603FR-07330RL; Manufacturer: YAGEO; Provided_By: Subcon
R31 = MCD-00220: Resistor,10K,0603,1%,1/10W; Manufacturer_Part_Number: RC0603FR-0710KL; Manufacturer: YAGEO; Provided_By: Subcon; Initial_Board_Reference: MB1319
R32 = MCD-00481: Resistor,47R,0402,1%,1/16W; Manufacturer_Part_Number: RC0402FR-0747RL; Manufacturer: YAGEO; Provided_By: SUBCO; ECCN_US: EAR99; ECCN_EU: NEC
SB1 SB9 SB12 SB13 SB15-SB32 SB40 SB41 = MCD-00071: as SB2 on sheet Arduino_extension_connectors
U9 U10 = MCD-00170: ESD protection 6V1; Part_Type: Diode; Manufacturer: STMICROELECTRONICS; ECCN_US: EAR99; ECCN_EU: NEC; Provided_By: Subcon; Initial_Board_Reference: MB1274
U13 = MCD-01243: STM32G474, LQFP64 package,  3D IC footprint with 2D socket footprint.; Manufacturer: STMICROELECTRONICS; BMS_Part_Number: 9175326; Provided_By: SUBCO with ST control; ECCN_US: 3A991A2; ECCN_EU: NEC
X2 = MCD-00091: Crystal 32.768kHz, 6pF, +-20ppm, 50Kohms max, SMD; Manufacturer_Part_Number: NX3215SA 32.768KHz EXS00A-MU00525; Manufacturer: NDK; Part_Type: Crystal_Osc; BMS_Part_Number: 9157034; ECCN_US: EAR99; ECCN_EU: NEC; Provided_By: SUBCO
X3 = MCD-01036: Crystal 24MHz, 6pF, +-20ppm, 80ohms max, SMD; Part_Type: Crystal_Osc; Manufacturer_Part_Number: NX2016SA 24MHz EXS00A-CS10820; Manufacturer: NDK; BMS_Part_Number: 9157045; ECCN_US: EAR99; ECCN_EU: NEC; Provided_By: SUBCO

## Sheet STM32_microcontroller_power.SchDoc: STM32 microcontroller power part
size A4; Date: Not used; ApprovedBy: Not used; CheckedBy: Not used; Author: Not used; CompanyName: STMicroelectronics; DrawnBy: Not used; Engineer: Not used; Organization: Not used; Address1: Not used; Address2: Not used; Address3: Not used; Address4: Not used; DocumentNumber: 4; Revision: Not used; SheetNumber: 4; SheetTotal: 8
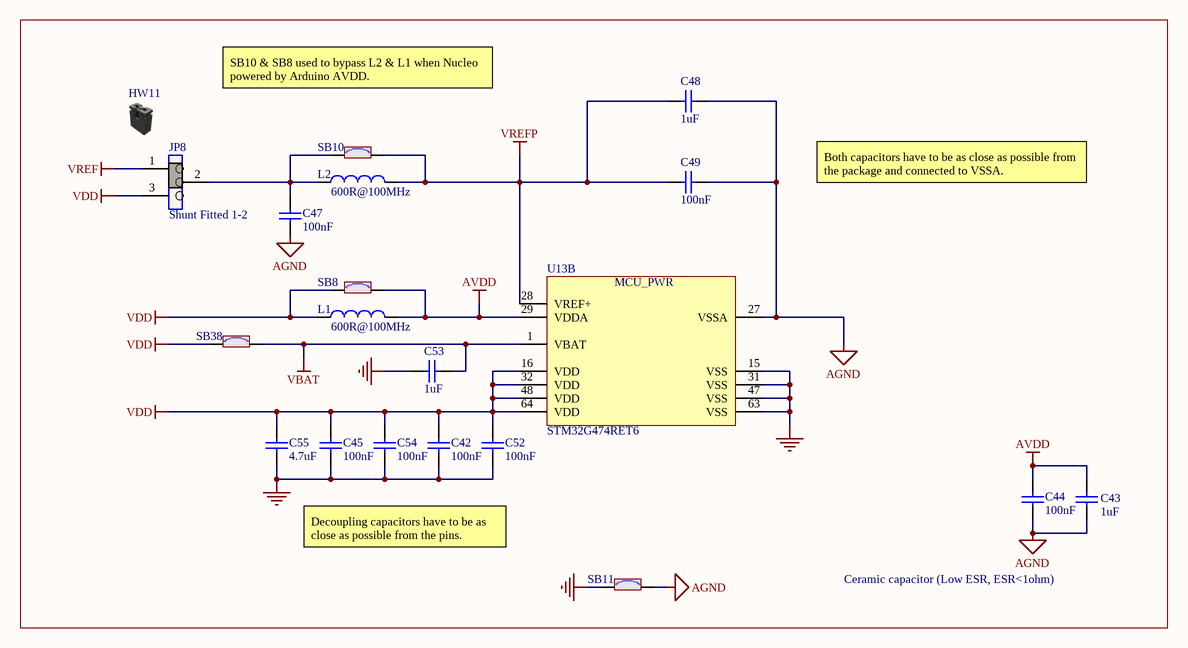
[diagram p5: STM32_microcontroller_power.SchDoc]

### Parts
C42  value 100nF  [C0402]
C43  value 1uF  [C0603]
C44  value 100nF  [C0402]
C45  value 100nF  [C0402]
C47  value 100nF  [C0402]
C48  value 1uF  [C0603]
C49  value 100nF  [C0402]
C52  value 100nF  [C0402]
C53  value 1uF  [C0603]
C54  value 100nF  [C0402]
C55  value 4.7uF  [C0603]
HW11  (no value)  (mechanical)
JP8  value Shunt Fitted 1-2  [CON_SAMTEC_TSW-103-07-F-S]
L1  value 600R@100MHz  [L0603]
L2  value 600R@100MHz  [L0603]
SB8  (no value)  [SOLDER-BRIDGE_R0603-0R]
SB10  (no value)  [SOLDER-BRIDGE_R0603-0R]
SB11  (no value)  [SOLDER-BRIDGE_R0603-0R]
SB38  (no value)  [SOLDER-BRIDGE_R0603-0R]
U13  value STM32G474RET6  [ICC_LQFP64_10X10_P050_SOCKET_YAMAICHI_IC149-064-069-B5_NM]  (part B of 2)

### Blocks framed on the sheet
Ceramic capacitor (Low ESR, ESR<1ohm): C42-C45 C47-C49 C52-C55 HW11 JP8 L1 L2 SB8 SB10 SB11 SB38 U13

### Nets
AGND: C43.1 C44.1 C47.1 C48.2 C49.2 SB11.2 U13.27(VSSA)
AVDD: C43.2 C44.2 L1.2 SB8.2 U13.29(VDDA)
GND: C42.1 C45.1 C52.1 C53.1 C54.1 C55.1 SB11.1 U13.15(VSS) U13.31(VSS) U13.47(VSS) U13.63(VSS)
VBAT: C53.2 SB38.2 U13.1(VBAT)
VDD: C42.2 C45.2 C52.2 C54.2 C55.2 JP8.3 L1.1 SB8.1 SB38.1 U13.16(VDD) U13.32(VDD) U13.48(VDD) U13.64(VDD)
VREF: JP8.1
VREFP: C48.1 C49.1 L2.2 SB10.2 U13.28(VREF+)
NetC47_2: C47.2 JP8.2 L2.1 SB10.1

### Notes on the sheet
- SB10 & SB8 used to bypass L2 & L1 when Nucleo powered by Arduino AVDD.
- Both capacitors have to be as close as possible from the package and connected to VSSA.
- Decoupling capacitors have to be as close as possible from the pins.

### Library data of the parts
C42 C44 C45 C47 C49 C52 C54 = MCD-00102: as C36 on sheet Power
C43 C48 C53 = MCD-00010: as C37 on sheet Power
C55 = MCD-00009: Capacitor, MLCC, 4.7uF, 16V, X5R, 10%, 0603, T=0.8mm; Manufacturer_Part_Number: CC0603KRX5R7BB475; Manufacturer: YAGEO; Provided_By: subcon; Initial_Board_Reference: MB1274
HW11 = MCD-00043: as HW5 on sheet Power
JP8 = MCD-00684: Header, 3x1, 2,54mm, VR, TH, Height 5.84mm/2.54mm - Shunt Fitted 1-2 by default; Part_Type: Connector; Manufacturer_Part_Number: TSW-103-07-F-S; Manufacturer: SAMTEC; Provided_By: SUBCO
L1 L2 = MCD-00047: SMD Chip ferrite bead, 600R@100MHz +/-25%, 350mA, 500mohm DC, 0603, T=0.8mm; Part_Type: Inductor; Manufacturer_Part_Number: FCM1608KF-601T03; Manufacturer: TAI-TECH; Provided_By: SUBCO
SB8 SB10 SB11 SB38 = MCD-00071: as SB2 on sheet Arduino_extension_connectors
U13 = MCD-01243: as U13 on sheet STM32_microcontroller_IOs

## Sheet ST_LINK_V3E.SchDoc: STLINK_V3E
size A3; Date: Not used; ApprovedBy: Not used; CheckedBy: Not used; Author: Not used; CompanyName: STMicroelectronics; DrawnBy: Not used; Engineer: Not used; Organization: Not used; Address1: Not used; Address2: Not used; Address3: Not used; Address4: Not used; DocumentNumber: 7; Revision: Not used; SheetNumber: 7; SheetTotal: 8
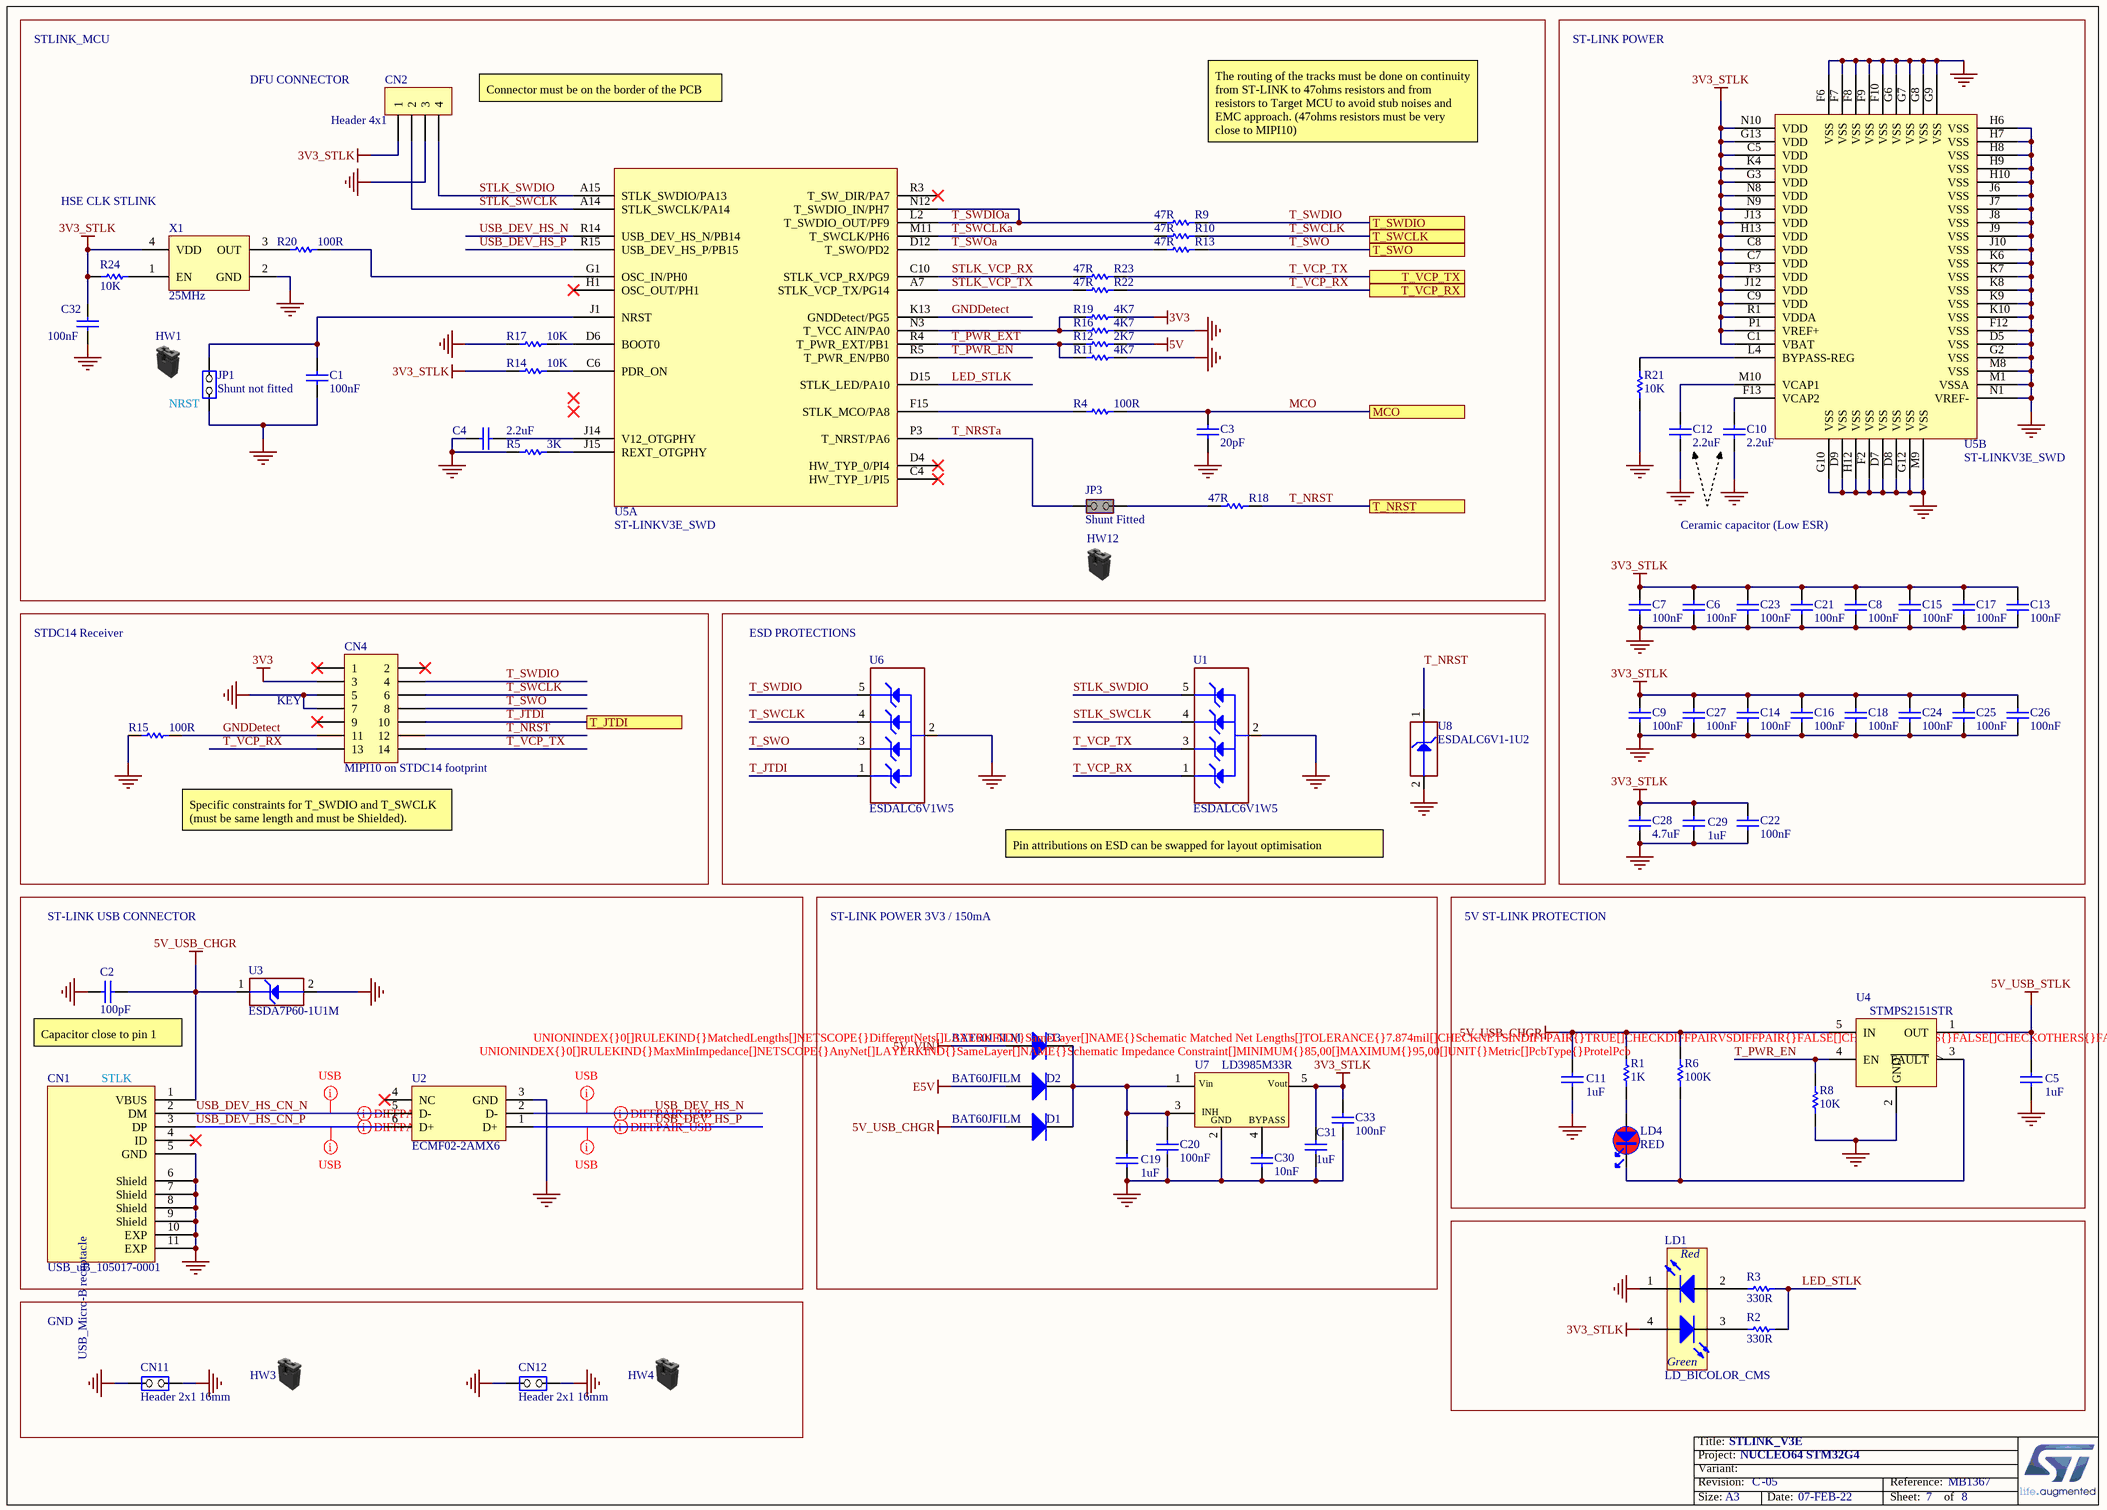
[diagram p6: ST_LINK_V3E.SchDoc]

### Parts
C1  value 100nF  [C0402]
C2  value 100pF  [C0402]
C3  value 20pF  [C0402]
C4  value 2.2uF  [C0603]
C5  value 1uF  [C0603]
C6  value 100nF  [C0402]
C7  value 100nF  [C0402]
C8  value 100nF  [C0402]
C9  value 100nF  [C0402]
C10  value 2.2uF  [C1206_H1P15]
C11  value 1uF  [C0603]
C12  value 2.2uF  [C1206_H1P15]
C13  value 100nF  [C0402]
C14  value 100nF  [C0402]
C15  value 100nF  [C0402]
C16  value 100nF  [C0402]
C17  value 100nF  [C0402]
C18  value 100nF  [C0402]
C19  value 1uF  [C0603]
C20  value 100nF  [C0402]
C21  value 100nF  [C0402]
C22  value 100nF  [C0402]
C23  value 100nF  [C0402]
C24  value 100nF  [C0402]
C25  value 100nF  [C0402]
C26  value 100nF  [C0402]
C27  value 100nF  [C0402]
C28  value 4.7uF  [C0603]
C29  value 1uF  [C0603]
C30  value 10nF  [C0402]
C31  value 1uF  [C0603]
C32  value 100nF  [C0402]
C33  value 100nF  [C0402]
CN1  value USB_uB_105017-0001  [CON_USBMICROB_MOLEX_105017-0001_H2P90]
CN2  value Header 4x1  [CON_SAMTEC_TSW-104-07-G-S]
CN4  value MIPI10 on STDC14 footprint  [CON_STDC14_Receiver_MEDIUM_WITH_MIPI10_3D]
CN11  value Header 2x1 16mm  [CON_SAMTEC_TSW-102-09-X-S]
CN12  value Header 2x1 16mm  [CON_SAMTEC_TSW-102-09-X-S]
D1  value BAT60JFILM  [DIO_SOD323]
D2  value BAT60JFILM  [DIO_SOD323]
D3  value BAT60JFILM  [DIO_SOD323]
HW1  (no value)  (mechanical)
HW3  (no value)  (mechanical)
HW4  (no value)  (mechanical)
HW12  (no value)  (mechanical)
JP1  value Shunt not fitted  [CON_SAMTEC_TSW-102-07-G-S]
JP3  Shunt Fitted  [CON_SAMTEC_TSW-102-07-G-S]
LD1  LD_BICOLOR_CMS  [LED_BI-GR_HSMF-A201-A00J1]
LD4  value RED  [LED_0603_RED_H0P4]  (hidden comment: LED_red)
R1  value 1K  [R0603]
R2  value 330R  [R0603]
R3  value 330R  [R0603]
R4  value 100R  [R0402]
R5  value 3K  [R0402]
R6  value 100K  [R0603]
R8  value 10K  [R0603]
R9  value 47R  [R0402]
R10  value 47R  [R0402]
R11  value 4K7  [R0402]
R12  value 2K7  [R0402]
R13  value 47R  [R0402]
R14  value 10K  [R0402]
R15  value 100R  [R0402]
R16  value 4K7  [R0402]
R17  value 10K  [R0402]
R18  value 47R  [R0402]
R19  value 4K7  [R0402]
R20  value 100R  [R0402]
R21  value 10K  [R0402]
R22  value 47R  [R0402]
R23  value 47R  [R0402]
R24  value 10K  [R0402]
U1  value ESDALC6V1W5  [ESD_SOT323-5L]
U2  value ECMF02-2AMX6  [ESD_QFN-6L_1P7X1P5_P050]  (hidden comment: ​)
U3  value ESDA7P60-1U1M  [ESD_QFN2_1P6X1_P125]
U4  value STMPS2151STR  [MOS_SOT23-5L]
U5  value ST-LINKV3E_SWD  [ICC_UFBGA201_176+25_10X10_P065]  (parts A,B of 2)
U6  value ESDALC6V1W5  [ESD_SOT323-5L]
U7  value LD3985M33R  [REG_SOT23-5L]
U8  value ESDALC6V1-1U2  [ESD_ST0201]
X1  value 25MHz  [OSC_NDK_NZ2520SB_4P]

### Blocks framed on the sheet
ESD PROTECTIONS: U1 U6 U8
ST-LINK POWER 3V3 / 150mA: C19 C20 C30 C31 C33 D1-D3 U7
5V ST-LINK PROTECTION: C5 C11 LD4 R1 R6 R8 U4
GND: CN11 CN12 HW3 HW4

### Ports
MCO, T_JTDI, T_NRST, T_SWCLK, T_SWDIO, T_SWO, T_VCP_RX, T_VCP_TX

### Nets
3V3: CN4.3 R19.2
3V3_STLK: C6.2 C7.2 C8.2 C9.2 C13.2 C14.2 C15.2 C16.2 C17.2 C18.2 C21.2 C22.2 C23.2 C24.2 C25.2 C26.2 C27.2 C28.2 C29.2 C31.2 C32.2 C33.2 CN2.1 LD1.4(YellowGreen_anode) R14.1 R24.1 U5.C1(VBAT) U5.C5(VDD) U5.C7(VDD) U5.C8(VDD) U5.C9(VDD) U5.F3(VDD) U5.G3(VDD) U5.G13(VDD) U5.H13(VDD) U5.J12(VDD) U5.J13(VDD) U5.K4(VDD) U5.N8(VDD) U5.N9(VDD) U5.N10(VDD) U5.P1(VREF+) U5.R1(VDDA) U7.5(Vout) X1.4(VDD)
5V: R12.1
5V_USB_CHGR: C2.2 C11.2 CN1.1(VBUS) D1.1(A) R1.2 R6.2 U3.1(IO1) U4.5(IN)
5V_USB_STLK: C5.2 U4.1(OUT)
5V_VIN: D3.1(A)
E5V: D2.1(A)
GND: C1.1 C2.1 C3.1 C4.1 C5.1 C6.1 C7.1 C8.1 C9.1 C10.1 C11.1 C12.1 C13.1 C14.1 C15.1 C16.1 C17.1 C18.1 C19.1 C20.1 C21.1 C22.1 C23.1 C24.1 C25.1 C26.1 C27.1 C28.1 C29.1 C30.1 C31.1 C32.1 C33.1 CN1.5(GND) CN1.6(Shield) CN1.7(Shield) CN1.8(Shield) CN1.9(Shield) CN1.10(EXP) CN1.11(EXP) CN2.3 CN4.5 CN4.7 CN11.1(COMMON) CN11.2(NO) CN12.1(COMMON) CN12.2(NO) JP1.1(COMMON) LD1.1(RED_cathode) R5.1 R8.2 R11.1 R15.1 R16.2 R17.1 R21.1 U1.2(GND) U2.3(GND) U3.2(GND) U4.2(GND) U5.D5(VSS) U5.D7(VSS) U5.D8(VSS) U5.D9(VSS) U5.F2(VSS) U5.F6(VSS) U5.F7(VSS) U5.F8(VSS) U5.F9(VSS) U5.F10(VSS) U5.F12(VSS) U5.G2(VSS) U5.G6(VSS) U5.G7(VSS) U5.G8(VSS) U5.G9(VSS) U5.G10(VSS) U5.G12(VSS) U5.H6(VSS) U5.H7(VSS) U5.H8(VSS) U5.H9(VSS) U5.H10(VSS) U5.H12(VSS) U5.J6(VSS) U5.J7(VSS) U5.J8(VSS) U5.J9(VSS) U5.J10(VSS) U5.K6(VSS) U5.K7(VSS) U5.K8(VSS) U5.K9(VSS) U5.K10(VSS) U5.M1(VSSA) U5.M8(VSS) U5.M9(VSS) U5.N1(VREF-) U6.2(GND) U7.2(GND) U8.2(GND) X1.2(GND)
GNDDetect: CN4.11 R15.2 U5.K13(GNDDetect/PG5)
LED_STLK: R2.2 R3.2 U5.D15(STLK_LED/PA10)
MCO: C3.2 R4.2 ; port MCO
STLK_SWCLK: CN2.2 U1.4(IO3) U5.A14(STLK_SWCLK/PA14)
STLK_SWDIO: CN2.4 U1.5(IO4) U5.A15(STLK_SWDIO/PA13)
STLK_VCP_RX: R23.1 U5.C10(STLK_VCP_RX/PG9)
STLK_VCP_TX: R22.1 U5.A7(STLK_VCP_TX/PG14)
T_JTDI: CN4.10 U6.1(IO1) ; port T_JTDI
T_NRST: CN4.12 R18.2 U8.1(IO1) ; port T_NRST
T_NRSTa: JP3.1(COMMON) U5.P3(T_NRST/PA6)
T_PWR_EN: R8.1 U4.4(EN) U5.R5(T_PWR_EN/PB0)
T_PWR_EXT: R11.2 R12.2 U5.R4(T_PWR_EXT/PB1)
T_SWCLK: CN4.6 R10.2 U6.4(IO3) ; port T_SWCLK
T_SWCLKa: R10.1 U5.M11(T_SWCLK/PH6)
T_SWDIO: CN4.4 R9.2 U6.5(IO4) ; port T_SWDIO
T_SWDIOa: R9.1 U5.L2(T_SWDIO_OUT/PF9) U5.N12(T_SWDIO_IN/PH7)
T_SWO: CN4.8 R13.2 U6.3(IO2) ; port T_SWO
T_SWOa: R13.1 U5.D12(T_SWO/PD2)
T_VCP_RX: CN4.13 R22.2 U1.1(IO1) ; port T_VCP_RX
T_VCP_TX: CN4.14 R23.2 U1.3(IO2) ; port T_VCP_TX
USB_DEV_HS_CN_N: CN1.2(DM) U2.5(D-)
USB_DEV_HS_CN_P: CN1.3(DP) U2.6(D+)
USB_DEV_HS_N: U2.2(D-) U5.R14(USB_DEV_HS_N/PB14)
USB_DEV_HS_P: U2.1(D+) U5.R15(USB_DEV_HS_P/PB15)
NetC1_2: C1.2 JP1.2(NO) U5.J1(NRST)
NetC4_2: C4.2 U5.J14(V12_OTGPHY)
NetC10_2: C10.2 U5.F13(VCAP2)
NetC12_2: C12.2 U5.M10(VCAP1)
NetC19_2: C19.2 C20.2 D1.2(K) D2.2(K) D3.2(K) U7.1(Vin) U7.3(CE)
NetC30_2: C30.2 U7.4(BYPASS)
NetJP3_2: JP3.2(NO) R18.1
NetLD1_2: LD1.2(Red_anode) R3.1
NetLD1_3: LD1.3(YellowGreen_cathode) R2.1
NetLD4_1: LD4.1 R1.1
NetLD4_2: LD4.2 R6.1 U4.3(~{FAULT})
NetR4_1: R4.1 U5.F15(STLK_MCO/PA8)
NetR5_2: R5.2 U5.J15(REXT_OTGPHY)
NetR14_2: R14.2 U5.C6(PDR_ON)
NetR16_1: R16.1 R19.1 U5.N3(T_VCC_AIN/PA0)
NetR17_2: R17.2 U5.D6(BOOT0)
NetR20_1: R20.1 X1.3(OUT)
NetR20_2: R20.2 U5.G1(OSC_IN/PH0)
NetR21_2: R21.2 U5.L4(BYPASS-REG)
NetR24_2: R24.2 X1.1(EN)

Not connected (* = marked no-connect by the designer): CN1 4(ID)*; CN4 1* 2* 9*; U2 4(NC)*; U5 C4(HW_TYP_1/PI5)* D4(HW_TYP_0/PI4)* H1(OSC_OUT/PH1)* R3(T_SW_DIR/PA7)*

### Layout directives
differential pair; rule Impedance Constraint [Min = 85.00    Max = 95.00    ]: USB_DEV_HS_CN_N, USB_DEV_HS_CN_P, USB_DEV_HS_N, USB_DEV_HS_P
rule Undefined; rule Matched Net Lengths [Tolerance = 0.2mm]; rule Impedance Constraint [Min = 85.00    Max = 95.00    ]: USB_DEV_HS_CN_N, USB_DEV_HS_CN_P, USB_DEV_HS_N, USB_DEV_HS_P

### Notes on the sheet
- STLINK_MCU
- ST-LINK POWER
- DFU CONNECTOR
- (near CN2) Connector must be on the border of the PCB
- The routing of the tracks must be done on continuity from ST-LINK to 47ohms resistors and from resistors to Target MCU to avoid stub noises and EMC approach. (47ohms resistors must be very close to MIPI10)
- HSE CLK STLINK
- (near JP1) NRST
- Ceramic capacitor (Low ESR)
- STDC14 Receiver
- (near CN4) KEY
- Specific constraints for T_SWDIO and T_SWCLK (must be same length and must be Shielded).
- Pin attributions on ESD can be swapped for layout optimisation
- ST-LINK USB CONNECTOR
- (near C2) Capacitor close to pin 1
- (near CN1) STLK

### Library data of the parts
C1 C6-C9 C13-C18 C20-C27 C32 C33 = MCD-00102: as C36 on sheet Power
C2 = MCD-00205: Capacitor, MLCC, 100pF, 50V, NPO, 5%, 0402, T=0,5mm; Manufacturer_Part_Number: CC0402JRNPO9BN101; Manufacturer: YAGEO; Provided_By: Subcon
C3 = MCD-00016: Capacitor, MLCC, 20pF, 50V, NPO, 5%, 0402, T=0,5mm; Manufacturer_Part_Number: CC0402JRNPO9BN200; Manufacturer: YAGEO; Provided_By: Subcon; Initial_Board_Reference: MB1274
C4 = MCD-00012: Capacitor, MLCC, 2.2uF, 10V, X5R, 10%, 0603, T=0,8mm; Manufacturer_Part_Number: CC0603KRX5R6BB225; Manufacturer: YAGEO; Alternate_Manufacturer_Part_Number: C0603C225K8PACTU; Alternate_Manufacturer: KEMET; Provided_By: Subcon; Initial_Board_Reference: MB1274
C5 C11 C19 C29 C31 = MCD-00010: as C37 on sheet Power
C10 C12 = MCD-00008: Capacitor, MLCC, 2.2uF, 16V, X7R, 10%, 1206, T=1,15mm; Manufacturer_Part_Number: CC1206KKX7R7BB225; Manufacturer: YAGEO; Alternate_Manufacturer_Part_Number: C1206C225K4RAC; Alternate_Manufacturer: KEMET; Provided_By: Subcon; Initial_Board_Reference: MB1274
C28 = MCD-00009: as C55 on sheet STM32_microcontroller_power
C30 = MCD-00011: Capacitor, MLCC, 10nF, 16V, X7R, 10%, 0402, T=0.5mm; Manufacturer_Part_Number: CC0402KRX7R7BB103; Manufacturer: YAGEO; Provided_By: Subcon; Initial_Board_Reference: MB1274
CN1 = MCD-00028: USB-MICRO-B, 0.65mm, RA, SMT, Bottom Mount,; Manufacturer_Part_Number: 1050170001; Manufacturer: MOLEX; Part_Type: Connector; Provided_By: Subcon; Initial_Board_Reference: MB1274
CN2 = MCD-00029: Header, 4x1, 2,54mm, VR, TH, Height 5.84mm/2.54mm; Manufacturer_Part_Number: TSW-104-07-x-S; Manufacturer: SAMTEC; Part_Type: Connector; Provided_By: Subcon; Initial_Board_Reference: MB1274
CN4 = MCD-01226: Header 5x2, 1.27mm, Dual row, Straight, Surface mount, vertical male connector. 3.05mm lead. Mates with FFSD connector. Footprint compatible with FTSH-107-01-L-DV,-K,-A,-P,-ES (STDC14 MEDIUM); Manufacturer_Part_Number: FTSH-105-01-L-DV-K; Manufacturer: SAMTEC; Alternate_Manufacturer_Part_Number: P127B-2x05MGF-079-0A; Alternate_Manufacturer: JIUBABA; Provided_By: SUBCO
CN11 CN12 = MCD-00214: Header, 2x1, 2,54mm, VR, TH, Height 5.84mm/10.16mm; Part_Type: Connector; Manufacturer_Part_Number: TSW-102-09-x-S; Manufacturer: SAMTEC; Provided_By: Subcon; Initial_Board_Reference: MB1319
D1-D3 = MCD-00034: BAT60JFILM; Manufacturer: STMICROELECTRONICS; Part_Type: Diode; ECCN_US: EAR99; ECCN_EU: NEC; Provided_By: Subcon; Initial_Board_Reference: MB1274
HW1 HW3 HW4 HW12 = MCD-00043: as HW5 on sheet Power
JP1 = MCD-00045: as JP7 on sheet STM32_microcontroller_IOs
JP3 = MCD-00683: as JP6 on sheet Power
LD1 = MCD-02402: LED Bicolor; Part_Type: Display; Part_Preference: Alternate; Manufacturer: EVERLIGHT; Manufacturer_Part_Number: 67-22sursygc-s530-a2-tr8; Alternate_Internal_Part_Number: MCD-00051; Alternate_EMS: C; ShowFields: YES; ID: 4508
LD4 = MCD-02787: LED, Red, VF : Min=1.7V , Max=2.2V, IF : 25mA, 0603 SMD; Part_Type: Display; Part_Preference: Recommended; Manufacturer: EVERLIGHT; Manufacturer_Part_Number: 19-217/R6C-AL1M2VY/6T; ShowFields: YES; ID: 4899
R1 = MCD-00070: as R30 on sheet Arduino_extension_connectors
R2 R3 = MCD-00197: as R27 on sheet STM32_microcontroller_IOs
R4 R15 R20 = MCD-00119: Resistor,100R,0402,1%,1/16W; Manufacturer_Part_Number: RC0402FR-07100RL; Manufacturer: YAGEO; Provided_By: Subcon; Initial_Board_Reference: MB1262
R5 = MCD-00185: Resistor,3K,0402,1%,1/16W; Manufacturer_Part_Number: RC0402FR-073KL; Manufacturer: YAGEO; Provided_By: Subcon
R6 = MCD-00223: as R28 on sheet Arduino_extension_connectors
R8 = MCD-00220: as R31 on sheet STM32_microcontroller_IOs
R9 R10 R13 R18 R22 R23 = MCD-00481: as R32 on sheet STM32_microcontroller_IOs
R11 R16 R19 = MCD-00065: Resistor,4K7,0402,1%,1/16W; Manufacturer_Part_Number: RC0402FR-074K7L; Manufacturer: YAGEO; Alternate_Manufacturer_Part_Number: RT0402FRE074K7L; Provided_By: Subcon; Initial_Board_Reference: MB1274
R12 = MCD-00055: Resistor,2K7,0402,1%,1/16W; Manufacturer_Part_Number: RC0402FR-072K7L; Manufacturer: YAGEO; Provided_By: Subcon; Initial_Board_Reference: MB1274
R14 R17 R21 R24 = MCD-00053: Resistor,10K,0402,1%,1/16W; Manufacturer_Part_Number: RC0402FR-0710KL; Manufacturer: YAGEO; Provided_By: subcon; Initial_Board_Reference: MB1274
U1 U6 = MCD-00136: Dual Transil array for ESD protection; Part_Type: Diode; Manufacturer: STMICROELECTRONICS; ECCN_US: EAR99; ECCN_EU: NEC; Provided_By: Subcon; Initial_Board_Reference: MB1262
U2 = MCD-00649: Common mode filter with ESD protection for USB 2.0 interface; Part_Type: Diode; Manufacturer: STMICROELECTRONICS; ECCN_US: EAR99; ECCN_EU: NEC; Provided_By: Subcon; Initial_Board_Reference: MB1248
U3 = MCD-00251: High power transient voltage suppressor, 7V breakdown; Part_Type: IC; Manufacturer: STMICROELECTRONICS; ECCN_US: EAR99; ECCN_EU: NEC; Provided_By: Subcon; Initial_Board_Reference: MB1311
U4 = MCD-00159: 500mA, Enhanced single channel power switches with active high enable pin; Part_Type: IC; Manufacturer: STMICROELECTRONICS; Alternate_Manufacturer_Part_Number: TPS2051C; Alternate_Manufacturer: TEXAS INSTRUMENTS; ECCN_US: EAR99; ECCN_EU: NEC; Provided_By: Subcon; Initial_Board_Reference: MB1264
U5 = MCD-00596: STM32F723IEK  (STM32F7) BGA176; Part_Type: IC; Manufacturer_Part_Number: STM32F723IEK6; Manufacturer: STMICROELECTRONICS; BMS_Part_Number: 9175300; Provided_By: SUBCO with ST control; ECCN_US: 3A991A2; ECCN_EU: NEC
U7 = MCD-00086: Ultra low drop-low noise BiCMOS voltage, regulators low ESR capacitors compatible; Manufacturer: STMICROELECTRONICS; Part_Type: IC; ECCN_US: EAR99; ECCN_EU: NEC; Provided_By: Subcon; Initial_Board_Reference: MB1274
U8 = MCD-00170: as U9 on sheet STM32_microcontroller_IOs
X1 = MCD-00597: Oscillator 25.00Mhz, -+50PPM, 3.3V, Temp -55 to +125°C; Manufacturer_Part_Number: NZ2520SB 25MHz END4869B; Manufacturer: NDK; Alternate_Manufacturer_Part_Number: KC2520B25.0000C10E00; Alternate_Manufacturer: AVX CORP/KYOCERA CORP; Part_Type: Crystal_Osc; Provided_By: STM; Initial_Board_Reference: MB1331

## Sheet Mechanical.SchDoc: Mechanical
size A4; Date: Not used; ApprovedBy: Not used; CheckedBy: Not used; Author: Not used; CompanyName: STMicroelectronics; DrawnBy: Not used; Engineer: Not used; Organization: Not used; Address1: Not used; Address2: Not used; Address3: Not used; Address4: Not used; DocumentNumber: 8; Revision: Not used; SheetNumber: 8; SheetTotal: 8
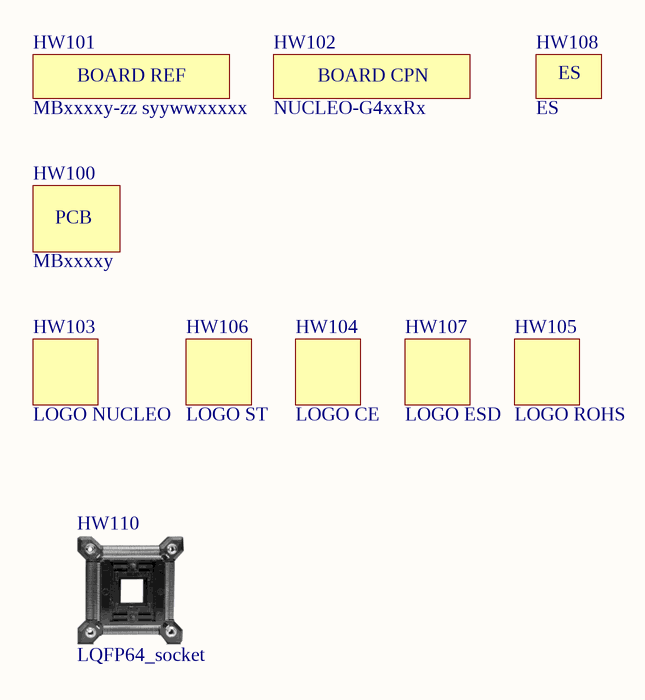
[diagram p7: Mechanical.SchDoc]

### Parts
HW100  value MBxxxxy  (mechanical)
HW101  value MBxxxxy-zz syywwxxxxx  [STICKER_25X9]  (mechanical)
HW102  value NUCLEO-G4xxRx  (mechanical)
HW103  value LOGO NUCLEO  [LOGO_NUCLEO]  (no BOM)
HW104  value LOGO CE  [LOGO_CE]  (no BOM)
HW105  value LOGO ROHS  [LOGO_ROHS]  (no BOM)
HW106  value LOGO ST  [LOGO_ST]  (no BOM)
HW107  value LOGO ESD  [LOGO_MAIN_1]  (no BOM)
HW108  value ES  (mechanical)
HW110  value LQFP64_socket  (hidden comment: SOCKET_LQFP64)  (mechanical)

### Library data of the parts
HW100 = MCD-00216: PCB, xxxx for PCB number, Y for PCB revision; Part_Type: Mechanical; Provided_By: SUBCO
HW101 = MCD-00235: Sticker to mention board reference + serial number; Part_Type: Mechanical; Provided_By: SUBCO
HW102 = MCD-00549: Product sticker to mention product CPN + product FG; Part_Type: Mechanical; Provided_By: Subcon; Initial_Board_Reference: MB1319
HW103 = MCD-00636: NUCLEO logo footprint for PCB; Part_Type: Mechanical; Manufacturer_Part_Number: NONE
HW104 = MCD-00626: CE logo footprint for PCB; Part_Type: Mechanical; Manufacturer_Part_Number: NONE
HW105 = MCD-00628: ROHS logo footprint for PCB; Part_Type: Mechanical; Manufacturer_Part_Number: NONE
HW106 = MCD-00625: STMicroelectronics logo footprint for PCB; Part_Type: Mechanical; Manufacturer_Part_Number: NONE
HW107 = MCD-00627: Hand ESD logo footprint for PCB; Part_Type: Mechanical; Manufacturer_Part_Number: NONE
HW108 = MCD-00234: Sticker to mention ES sample; Part_Type: Mechanical; Provided_By: SUBCO
HW110 = MCD-01253: Yamaichi socket for LQFP64, with positioning pins.; Part_Type: Misc; Manufacturer_Part_Number: IC149-064-169-B5; Provided_By: SUBCO

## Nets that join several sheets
3V3: Arduino_extension_connectors (CN6.4 CN7.16 R25.1 SB39.1), Power (JP6.1 SB5.2), ST_LINK_V3E (CN4.3 R19.2)
5V: Arduino_extension_connectors (CN6.5 CN7.18), Power (11 pins), ST_LINK_V3E (R12.1)
5V_USB_CHGR: Arduino_extension_connectors (CN10.8), Power (JP5.7), ST_LINK_V3E (8 pins)
5V_USB_STLK: Power (JP5.1), ST_LINK_V3E (C5.2 U4.1)
5V_VIN: Arduino_extension_connectors (R30.2), Power (C38.2 JP5.3 U11.2 U11.4), ST_LINK_V3E (D3.1)
AGND: Arduino_extension_connectors (CN10.32), Power (C46.1 C50.1 R34.1 U14.5), STM32_microcontroller_power (7 pins)
E5V: Arduino_extension_connectors (CN7.6), Power (JP5.5), ST_LINK_V3E (D2.1)
GND: Arduino_extension_connectors (11 pins), Power (10 pins), STM32_microcontroller_IOs (14 pins), STM32_microcontroller_power (11 pins), ST_LINK_V3E (102 pins)
VBAT: Arduino_extension_connectors (CN7.33), STM32_microcontroller_power (C53.2 SB38.2 U13.1)
VDD: Arduino_extension_connectors (CN7.5), Power (JP6.2), STM32_microcontroller_IOs (B1.1 B1.2), STM32_microcontroller_power (13 pins)
VIN: Arduino_extension_connectors (CN6.8 CN7.24), Power (C41.2 U11.3)
VREF: Power (5 pins), STM32_microcontroller_power (JP8.1)
VREFP: Arduino_extension_connectors (CN5.8 CN10.7), STM32_microcontroller_power (5 pins)
ARD_D0_RX: Arduino_extension_connectors (CN9.1 CN10.37), STM32_microcontroller_IOs (SB19.2 SB22.2)
ARD_D1_TX: Arduino_extension_connectors (CN9.2 CN10.35), STM32_microcontroller_IOs (SB13.2 SB18.2)
MCO: STM32_microcontroller_IOs (SB27.1), ST_LINK_V3E (C3.2 R4.2)
PA0: Arduino_extension_connectors (CN7.28 CN8.1), STM32_microcontroller_IOs (SB21.2 U13.12)
PA1: Arduino_extension_connectors (CN7.30 CN8.2), STM32_microcontroller_IOs (U13.13)
PA4: Arduino_extension_connectors (CN7.32 CN8.3), STM32_microcontroller_IOs (U13.18)
PA5: Arduino_extension_connectors (CN5.6 CN10.11 SB6.1), STM32_microcontroller_IOs (U13.19)
PA6: Arduino_extension_connectors (CN5.5 CN10.13), STM32_microcontroller_IOs (U13.20)
PA7: Arduino_extension_connectors (CN5.4 CN10.15), STM32_microcontroller_IOs (U13.21)
PA8: Arduino_extension_connectors (CN9.8 CN10.23), STM32_microcontroller_IOs (U13.42)
PA9: Arduino_extension_connectors (CN5.1 CN10.21), STM32_microcontroller_IOs (U13.43)
PA10: Arduino_extension_connectors (CN9.3 CN10.33), STM32_microcontroller_IOs (U13.44)
PA11: Arduino_extension_connectors (CN10.14), STM32_microcontroller_IOs (U13.45)
PA12: Arduino_extension_connectors (CN10.12), STM32_microcontroller_IOs (U13.46)
PA13: Arduino_extension_connectors (CN7.13), STM32_microcontroller_IOs (SB40.2 U13.49)
PA14: Arduino_extension_connectors (CN7.15), STM32_microcontroller_IOs (SB41.2 U13.50)
PA15: Arduino_extension_connectors (SB7.1 SB37.2), STM32_microcontroller_IOs (R32.2 U13.51)
PB0: Arduino_extension_connectors (CN7.34 CN8.4), STM32_microcontroller_IOs (U13.24)
PB1: Arduino_extension_connectors (CN10.24), STM32_microcontroller_IOs (U13.25)
PB2: Arduino_extension_connectors (CN10.22), STM32_microcontroller_IOs (U13.26)
PB3: Arduino_extension_connectors (CN9.4 CN10.31), STM32_microcontroller_IOs (SB15.1 U13.56)
PB4: Arduino_extension_connectors (CN9.6 CN10.27), STM32_microcontroller_IOs (U13.57)
PB5: Arduino_extension_connectors (CN9.5 CN10.29), STM32_microcontroller_IOs (U13.58)
PB6: Arduino_extension_connectors (CN5.3 CN10.17), STM32_microcontroller_IOs (U13.59)
PB7: Arduino_extension_connectors (CN7.21), STM32_microcontroller_IOs (U13.60)
PB8: Arduino_extension_connectors (SB2.2 SB4.1), STM32_microcontroller_IOs (JP7.1 U13.61)
PB9: Arduino_extension_connectors (CN5.9 CN10.5 SB34.2), STM32_microcontroller_IOs (U13.62)
PB10: Arduino_extension_connectors (CN9.7 CN10.25), STM32_microcontroller_IOs (U13.30)
PB11: Arduino_extension_connectors (CN10.18), STM32_microcontroller_IOs (U13.33)
PB12: Arduino_extension_connectors (CN10.16), STM32_microcontroller_IOs (U13.34)
PB13: Arduino_extension_connectors (CN10.30), STM32_microcontroller_IOs (U13.35)
PB14: Arduino_extension_connectors (CN10.28), STM32_microcontroller_IOs (U13.36)
PB15: Arduino_extension_connectors (CN10.26), STM32_microcontroller_IOs (U13.37)
PC0: Arduino_extension_connectors (SB36.1), STM32_microcontroller_IOs (U13.8)
PC1: Arduino_extension_connectors (SB35.1), STM32_microcontroller_IOs (U13.9)
PC2: Arduino_extension_connectors (CN7.35), STM32_microcontroller_IOs (U13.10)
PC3: Arduino_extension_connectors (CN7.37), STM32_microcontroller_IOs (U13.11)
PC4: Arduino_extension_connectors (SB33.2), STM32_microcontroller_IOs (SB12.2 SB13.1 U13.22)
PC5: Arduino_extension_connectors (SB3.2), STM32_microcontroller_IOs (SB19.1 SB20.2 U13.23)
PC6: Arduino_extension_connectors (CN10.4), STM32_microcontroller_IOs (U13.38)
PC7: Arduino_extension_connectors (CN5.2 CN10.19), STM32_microcontroller_IOs (U13.39)
PC8: Arduino_extension_connectors (CN10.2), STM32_microcontroller_IOs (U13.40)
PC9: Arduino_extension_connectors (CN10.1), STM32_microcontroller_IOs (U13.41)
PC10: Arduino_extension_connectors (CN7.1), STM32_microcontroller_IOs (U13.52)
PC11: Arduino_extension_connectors (CN7.2), STM32_microcontroller_IOs (U13.53)
PC12: Arduino_extension_connectors (CN7.3), STM32_microcontroller_IOs (U13.54)
PC13: Arduino_extension_connectors (CN7.23), STM32_microcontroller_IOs (SB16.2 U13.2)
PC14: Arduino_extension_connectors (CN7.25), STM32_microcontroller_IOs (SB32.1)
PC15: Arduino_extension_connectors (CN7.27), STM32_microcontroller_IOs (SB29.1)
PD2: Arduino_extension_connectors (CN7.4), STM32_microcontroller_IOs (U13.55)
PF0: Arduino_extension_connectors (CN7.29), STM32_microcontroller_IOs (SB28.1)
PF1: Arduino_extension_connectors (CN7.31), STM32_microcontroller_IOs (SB24.1)
T_JTDI: STM32_microcontroller_IOs (SB9.1), ST_LINK_V3E (CN4.10 U6.1)
T_NRST: Arduino_extension_connectors (CN6.3 CN7.14), STM32_microcontroller_IOs (5 pins), ST_LINK_V3E (CN4.12 R18.2 U8.1)
T_SWCLK: STM32_microcontroller_IOs (SB41.1), ST_LINK_V3E (CN4.6 R10.2 U6.4)
T_SWDIO: STM32_microcontroller_IOs (SB40.1), ST_LINK_V3E (CN4.4 R9.2 U6.5)
T_SWO: STM32_microcontroller_IOs (SB15.2), ST_LINK_V3E (CN4.8 R13.2 U6.3)
T_VCP_RX: STM32_microcontroller_IOs (SB20.1 SB23.1), ST_LINK_V3E (CN4.13 R22.2 U1.1)
T_VCP_TX: STM32_microcontroller_IOs (SB12.1 SB17.1), ST_LINK_V3E (CN4.14 R23.2 U1.3)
